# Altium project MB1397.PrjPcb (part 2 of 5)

## Sheet Audio.SchDoc: Audio
size A4; Date: Not used; ApprovedBy: Not used; CheckedBy: Not used; Author: Not used; CompanyName: STMicroelectronics; DrawnBy: Not used; Engineer: Not used; Organization: Not used; Address1: Not used; Address2: Not used; Address3: Not used; Address4: Not used; DocumentNumber: Not used; Revision: Not used; SheetNumber: 9; SheetTotal: 22
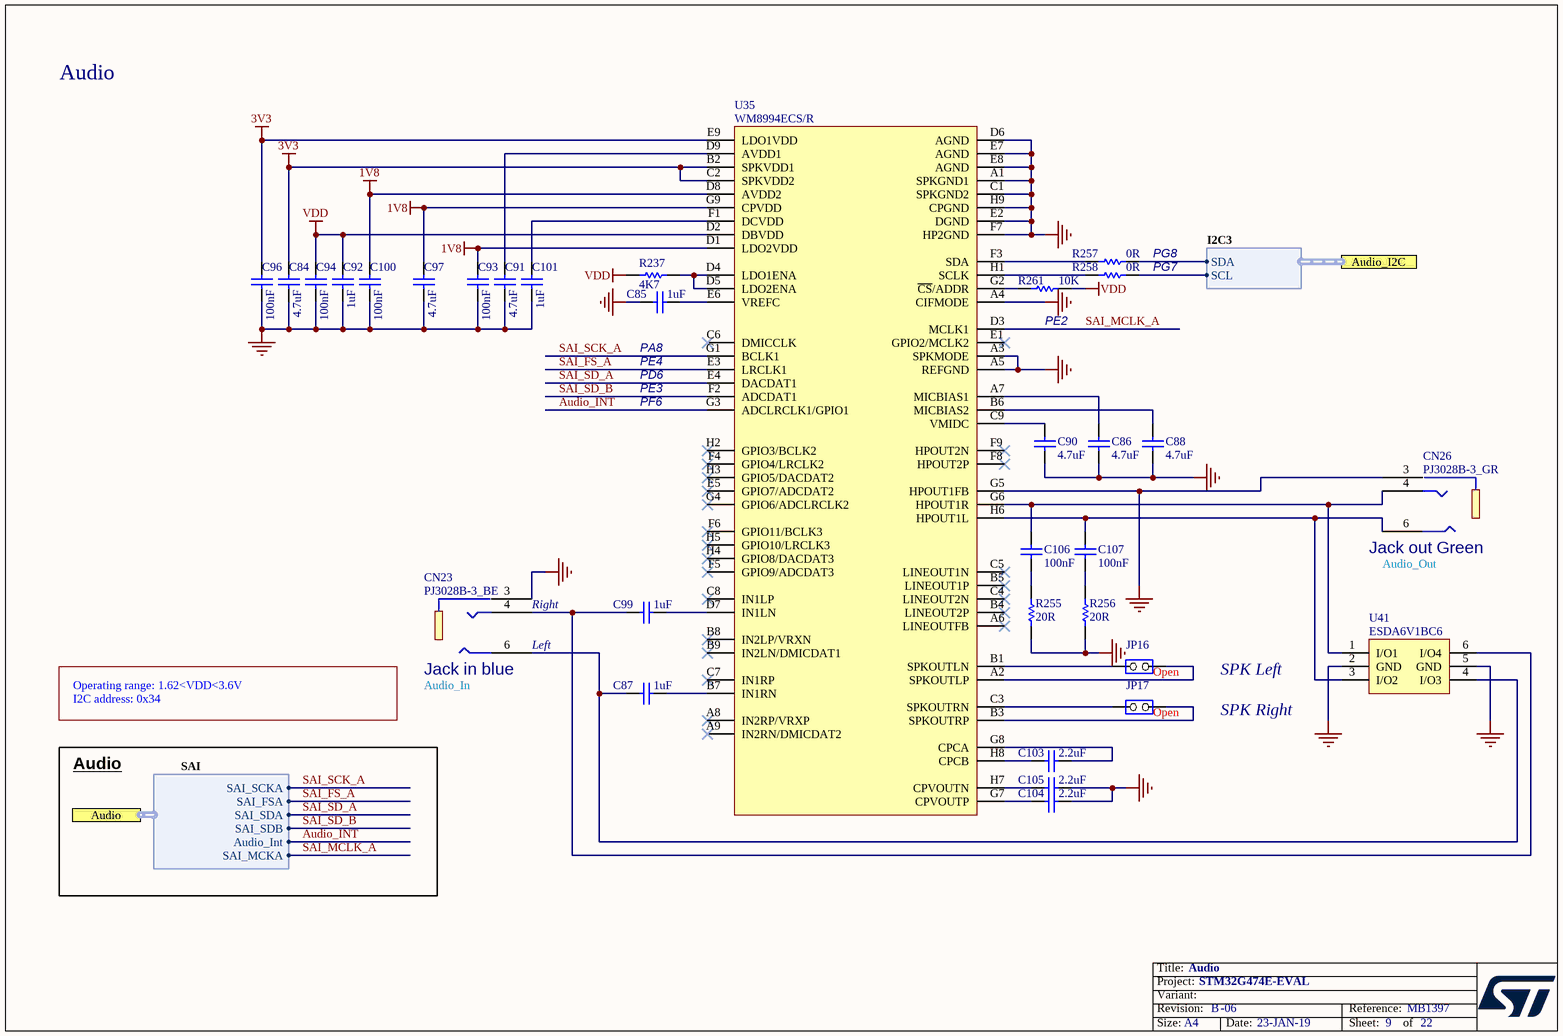
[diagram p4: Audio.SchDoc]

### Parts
C84  value 4.7uF  [C0603]  (hidden comment: Capacitor)
C85  value 1uF  [C0603]  (hidden comment: Capacitor)
C86  value 4.7uF  [C0603]  (hidden comment: Capacitor)
C87  value 1uF  [C0603]  (hidden comment: Capacitor)
C88  value 4.7uF  [C0603]  (hidden comment: Capacitor)
C90  value 4.7uF  [C0603]  (hidden comment: Capacitor)
C91  value 4.7uF  [C0603]  (hidden comment: Capacitor)
C92  value 1uF  [C0603]  (hidden comment: Capacitor)
C93  value 100nF  [C0402]  (hidden comment: Capacitor)
C94  value 100nF  [C0402]  (hidden comment: Capacitor)
C96  value 100nF  [C0402]  (hidden comment: Capacitor)
C97  value 4.7uF  [C0603]  (hidden comment: Capacitor)
C99  value 1uF  [C0603]  (hidden comment: Capacitor)
C100  value 100nF  [C0402]  (hidden comment: Capacitor)
C101  value 1uF  [C0603]  (hidden comment: Capacitor)
C103  value 2.2uF  [C0603]  (hidden comment: Capacitor)
C104  value 2.2uF  [C0603]  (hidden comment: Capacitor)
C105  value 2.2uF  [C0603]  (hidden comment: Capacitor)
C106  value 100nF  [C0402]  (hidden comment: Capacitor)
C107  value 100nF  [C0402]  (hidden comment: Capacitor)
CN23  value PJ3028B-3_BE  [CON_PHONE-JACK-3P5_HY_PJ3028B]  (hidden comment: Jack_PJ3028B-3_3P)
CN26  value PJ3028B-3_GR  [CON_PHONE-JACK-3P5_HY_PJ3028B]  (hidden comment: Jack_PJ3028B-3_3P)
JP16  Jumper_Header 2x1  [CON_SAMTEC_TSW-102-07-G-S]  (value not drawn)
JP17  Jumper_Header 2x1  [CON_SAMTEC_TSW-102-07-G-S]  (value not drawn)
R237  value 4K7  [R0402]  (hidden comment: Resistor)
R255  value 20R  [R0603]  (hidden comment: Resistor)
R256  value 20R  [R0603]  (hidden comment: Resistor)
R257  value 0R  [R0603]  (hidden comment: Resistor)
R258  value 0R  [R0603]  (hidden comment: Resistor)
R261  value 10K  [R0402]  (hidden comment: Resistor)
U35  WM8994ECS/R  [ICC_W-CSP-BGA72_4P511X4P023_P050]
U41  ESDA6V1BC6  [ESD_SOT23-6L]

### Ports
Audio (harness SAI), Audio_I2C (harness I2C3)

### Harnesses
I2C3: SDA, SCL
SAI: SAI_SDB, SAI_FSA, Audio_Int, SAI_SDA, SAI_SCKA, SAI_MCKA

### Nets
1V8: C93.1 C97.2 C100.1 U35.D1(LDO2VDD) U35.D8(AVDD2) U35.G9(CPVDD)
3V3: C84.2 C96.1 U35.B2(SPKVDD1) U35.C2(SPKVDD2) U35.E9(LDO1VDD)
GND: C84.1 C85.2 C86.1 C88.1 C90.1 C91.1 C92.1 C93.2 C94.2 C96.2 C97.1 C100.2 C101.1 C104.1 C105.1 CN23.3 CN26.3 R255.1 R256.1 U35.A1(SPKGND1) U35.A3(SPKMODE) U35.A4(CIFMODE) U35.A5(REFGND) U35.C1(SPKGND2) U35.D6(AGND) U35.E2(DGND) U35.E7(AGND) U35.E8(AGND) U35.F7(HP2GND) U35.G5(HPOUT1FB) U35.H9(CPGND) U41.2(GND) U41.5(GND)
VDD: C92.2 C94.1 R237.1 R261.1 U35.D2(DBVDD)
Audio_INT: U35.G3(ADCLRCLK1/GPIO1) ; port Audio.Audio_Int
SAI_FS_A: U35.E3(LRCLK1) ; port Audio.SAI_FSA
SAI_MCLK_A: U35.D3(MCLK1) ; port Audio.SAI_MCKA
SAI_SCK_A: U35.G1(BCLK1) ; port Audio.SAI_SCKA
SAI_SD_A: U35.E4(DACDAT1) ; port Audio.SAI_SDA
SAI_SD_B: U35.F2(ADCDAT1) ; port Audio.SAI_SDB
NetC85_1: C85.1 U35.E6(VREFC)
NetC86_2: C86.2 U35.A7(MICBIAS1)
NetC87_1: C87.1 U35.B7(IN1RN)
NetC87_2: C87.2 CN23.6 U41.4(I/O3)
NetC88_2: C88.2 U35.B6(MICBIAS2)
NetC90_2: C90.2 U35.C9(VMIDC)
NetC91_2: C91.2 U35.D9(AVDD1)
NetC99_1: C99.1 U35.D7(IN1LN)
NetC99_2: C99.2 CN23.4 U41.6(I/O4)
NetC101_2: C101.2 U35.F1(DCVDD)
NetC103_1: C103.1 U35.G8(CPCA)
NetC103_2: C103.2 U35.H8(CPCB)
NetC104_2: C104.2 U35.G7(CPVOUTP)
NetC105_2: C105.2 U35.H7(CPVOUTN)
NetC106_1: C106.1 CN26.4 U35.G6(HPOUT1R) U41.1(I/O1)
NetC106_2: C106.2 R255.2
NetC107_1: C107.1 CN26.6 U35.H6(HPOUT1L) U41.3(I/O2)
NetC107_2: C107.2 R256.2
NetJP16_1: JP16.1(COMMON) U35.A2(SPKOUTLP)
NetJP16_2: JP16.2(NO) U35.B1(SPKOUTLN)
NetJP17_1: JP17.1(COMMON) U35.B3(SPKOUTRP)
NetJP17_2: JP17.2(NO) U35.C3(SPKOUTRN)
NetR237_2: R237.2 U35.D4(LDO1ENA) U35.D5(LDO2ENA)
NetR257_1: R257.1 U35.F3(SDA)
NetR257_2: R257.2 ; port Audio_I2C.SDA
NetR258_1: R258.1 U35.H1(SCLK)
NetR258_2: R258.2 ; port Audio_I2C.SCL
NetR261_2: R261.2 U35.G2(~{CS}/ADDR)

Not connected (* = marked no-connect by the designer): U35 A6(LINEOUTFB)* A8(IN2RP/VRXP)* A9(IN2RN/DMICDAT2)* B4(LINEOUT2P)* B5(LINEOUT1P)* B8(IN2LP/VRXN)* B9(IN2LN/DMICDAT1)* C4(LINEOUT2N)* C5(LINEOUT1N)* C6(DMICCLK)* C7(IN1RP)* C8(IN1LP)* E1(GPIO2/MCLK2)* E5(GPIO7/ADCDAT2)* F4(GPIO4/LRCLK2)* F5(GPIO9/ADCDAT3)* F6(GPIO11/BCLK3)* F8(HPOUT2P)* F9(HPOUT2N)* G4(GPIO6/ADCLRCLK2)* H2(GPIO3/BCLK2)* H3(GPIO5/DACDAT2)* H4(GPIO8/DACDAT3)* H5(GPIO10/LRCLK3)*

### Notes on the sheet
- Audio
- PG8
- PG7
- (near C85) PA8
- PD6
- PE4
- (near R261) PE2
- PE3
- PF6
- (near CN26) Jack out Green
- (near CN26) Audio_Out
- (near CN23) Right
- (near CN23) Left
- Operating range: 1.62<VDD<3.6V
- I2C address: 0x34
- (near CN23) Jack in blue
- (near CN23) Audio_In
- (near JP16) Open
- (near JP17) Open
- SPK Left
- SPK Right

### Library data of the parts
C84 C86 C88 C90 C91 C97 = MCD-00009: Capacitor, MLCC, 4.7uF, 16V, X5R, 10%, 0603, T=0.8mm; Manufacturer_Part_Number: CC0603KRX5R7BB475; Manufacturer: YAGEO; Provided_By: SUBCO; Initial_Board_Reference: MB1274; Path: ws/MCD_ApplicationBoards/Lists/MCDPARTSdatabase; Item Type: Item
C85 C87 C92 C99 C101 = MCD-00010: Capacitor, MLCC, 1uF, 16V, X5R, 10%, 0603, T=0,8mm; Manufacturer_Part_Number: CC0603KRX5R7BB105; Manufacturer: YAGEO; Provided_By: SUBCO; Initial_Board_Reference: MB1274; Path: ws/MCD_ApplicationBoards/Lists/MCDPARTSdatabase; Item Type: Item
C93 C94 C96 C100 C106 C107 = MCD-00006: Capacitor, MLCC, 100nF, 16V, X7R, 10%, 0402, T=0.5mm; Manufacturer_Part_Number: CC0402KRX7R7BB104; Manufacturer: YAGEO; Alternate_Manufacturer_Part_Number: GCM155R71C104KA55D; Alternate_Manufacturer: MURATA; Provided_By: SUBCO; Initial_Board_Reference: MB1274; Path: ws/MCD_ApplicationBoards/Lists/MCDPARTSdatabase; Item Type: Item
C103-C105 = MCD-00012: Capacitor, MLCC, 2.2uF, 10V, X5R, 10%, 0603, T=0,8mm; Manufacturer_Part_Number: CC0603KRX5R6BB225; Manufacturer: YAGEO; Alternate_Manufacturer_Part_Number: C0603C225K8PACTU; Alternate_Manufacturer: KEMET; Provided_By: SUBCO; Initial_Board_Reference: MB1274; Path: ws/MCD_ApplicationBoards/Lists/MCDPARTSdatabase; Item Type: Item
CN23 = MCD-00682: Connector Jack socket Stereo 3.5mm, 3 pins, RA, SMT, Blue (Line input); Manufacturer: QIAOD; Alternate_Manufacturer_Part_Number: PJ30280-3_BE; Provided_By: SUBCO; Initial_Board_Reference: MB1260; Path: ws/MCD_ApplicationBoards/Lists/MCDPARTSdatabase; Item Type: Item
CN26 = MCD-00018: Connector Jack socket Stereo 3.5mm, 3 pins, RA, SMT, Green (Line output); Manufacturer: QIAOD; Alternate_Manufacturer_Part_Number: PJ30280-3_GR; Provided_By: SUBCO; Initial_Board_Reference: MB1274; Path: ws/MCD_ApplicationBoards/Lists/MCDPARTSdatabase; Item Type: Item
JP16 JP17 = MCD-00045: Header, 2x1, 2,54mm, VR, TH, Height 5.84mm/2.54mm; Part_Type: Connector; Manufacturer_Part_Number: TSW-102-07-x-S; Manufacturer: SAMTEC; Value: Shunt not fitted; Provided_By: SUBCO; Initial_Board_Reference: MB1274; Path: ws/MCD_ApplicationBoards/Lists/MCDPARTSdatabase; Item Type: Item
R237 = MCD-00065: Resistor,4K7,0402,1%,1/16W; Manufacturer_Part_Number: RC0402FR-074K7L; Manufacturer: YAGEO; Alternate_Manufacturer_Part_Number: RT0402FRE074K7L; Provided_By: SUBCO; Initial_Board_Reference: MB1274; Path: ws/MCD_ApplicationBoards/Lists/MCDPARTSdatabase; Item Type: Item
R255 R256 = MCD-00345: Resistor,20R,0603,1%,1/10W; Manufacturer_Part_Number: RC0603FR-0720RL; Manufacturer: YAGEO; Provided_By: SUBCO; Initial_Board_Reference: MBxxxx; Path: ws/MCD_ApplicationBoards/Lists/MCDPARTSdatabase; Item Type: Item
R257 R258 = MCD-00056: Resistor,0R,0603,5%,1/10W; Manufacturer_Part_Number: RC0603JR-070RL; Manufacturer: YAGEO; Provided_By: SUBCO; Initial_Board_Reference: MB1274; Path: ws/MCD_ApplicationBoards/Lists/MCDPARTSdatabase; Item Type: Item
R261 = MCD-00053: Resistor,10K,0402,1%,1/16W; Manufacturer_Part_Number: RC0402FR-0710KL; Manufacturer: YAGEO; Provided_By: SUBCO; Initial_Board_Reference: MB1274; Path: ws/MCD_ApplicationBoards/Lists/MCDPARTSdatabase; Item Type: Item
U35 = MCD-00079: Multi-Channel Audio Hub CODEC for Smartphones; Part_Type: IC; Manufacturer: CIRRUS LOGIC; Provided_By: SUBCO; Initial_Board_Reference: MB1274; Path: ws/MCD_ApplicationBoards/Lists/MCDPARTSdatabase; Item Type: Item
U41 = MCD-00247: Quad Bidir ESD protection; Part_Type: Diode; Manufacturer: STMICROELECTRONICS; BMS_Part_Number: 9179038; Provided_By: SUBCO with ST control; Initial_Board_Reference: MB1311; Path: ws/MCD_ApplicationBoards/Lists/MCDPARTSdatabase; Item Type: Item

## Sheet QSPI_Memory.SchDoc: QSPI Memory
size A4; Date: Not used; ApprovedBy: Not used; CheckedBy: Not used; Author: Not used; CompanyName: STMicroelectronics; DrawnBy: Not used; Engineer: Not used; Organization: Not used; Address1: Not used; Address2: Not used; Address3: Not used; Address4: Not used; DocumentNumber: Not used; Revision: Not used; SheetNumber: 8; SheetTotal: 22
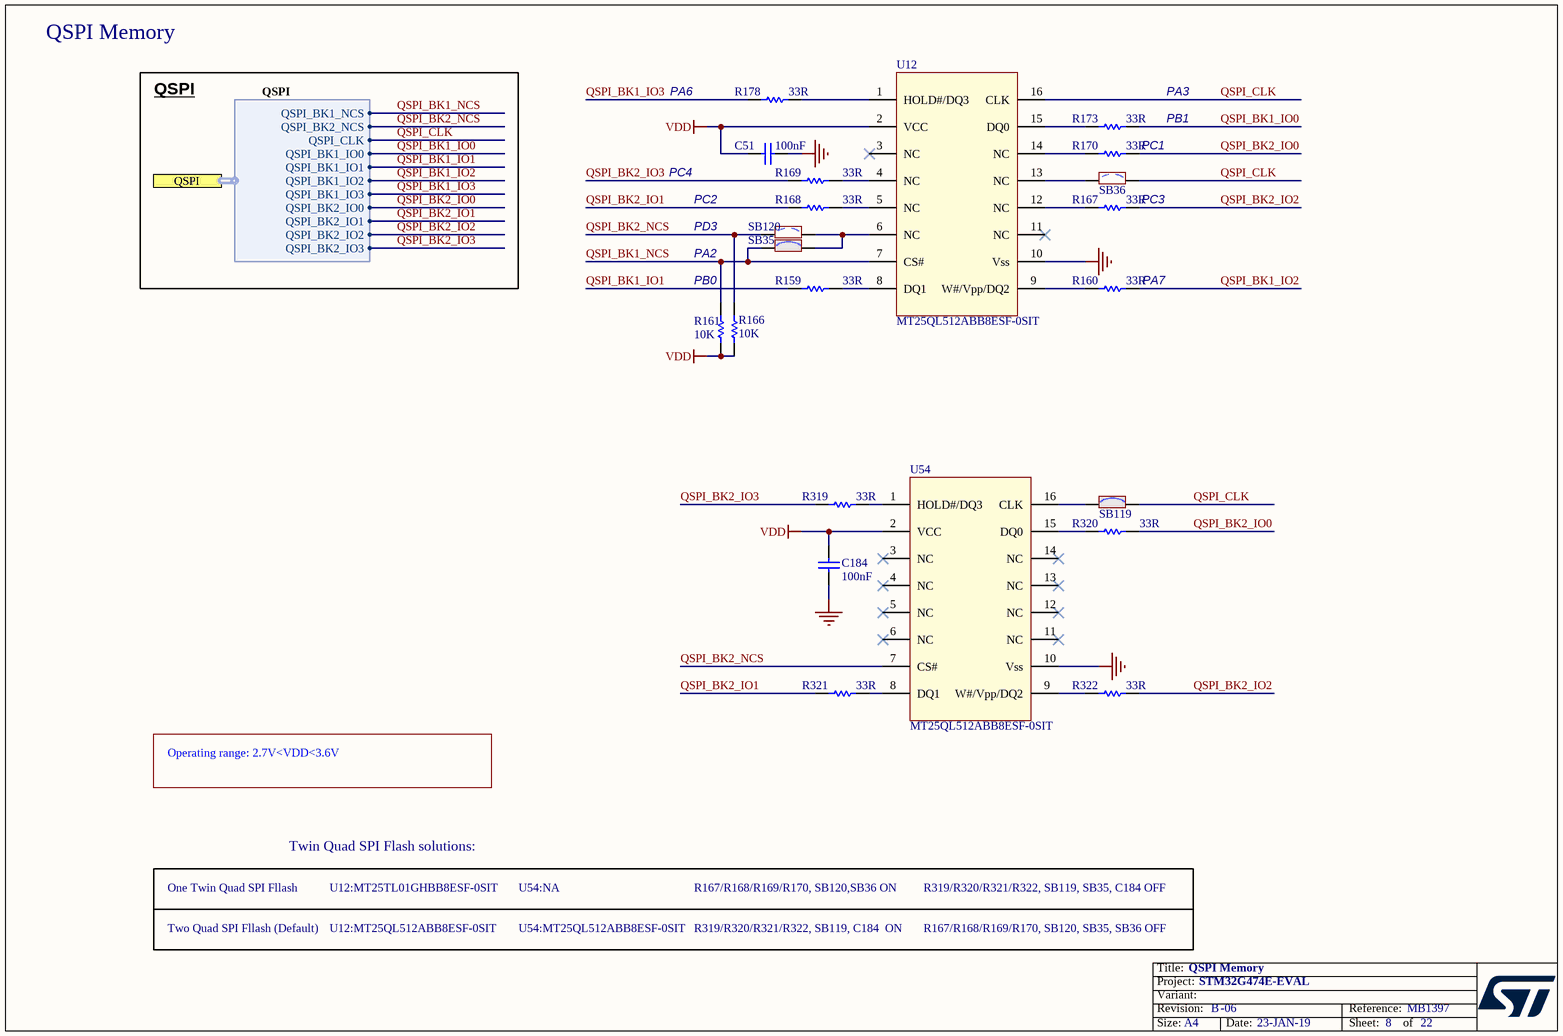
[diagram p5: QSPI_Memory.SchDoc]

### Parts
C51  value 100nF  [C0402]  (hidden comment: Capacitor)
C184  value 100nF  [C0402]  (hidden comment: Capacitor)
R159  value 33R  [R0402]  (hidden comment: Resistor)
R160  value 33R  [R0402]  (hidden comment: Resistor)
R161  value 10K  [R0402]  (hidden comment: Resistor)
R166  value 10K  [R0402]  (hidden comment: Resistor)
R167  value 33R  [R0402]  (hidden comment: Resistor)
R168  value 33R  [R0402]  (hidden comment: Resistor)
R169  value 33R  [R0402]  (hidden comment: Resistor)
R170  value 33R  [R0402]  (hidden comment: Resistor)
R173  value 33R  [R0402]  (hidden comment: Resistor)
R178  value 33R  [R0402]  (hidden comment: Resistor)
R319  value 33R  [R0402]  (hidden comment: Resistor)
R320  value 33R  [R0402]  (hidden comment: Resistor)
R321  value 33R  [R0402]  (hidden comment: Resistor)
R322  value 33R  [R0402]  (hidden comment: Resistor)
SB35  SB_ON  [SOLDER-BRIDGE_R0603-0R]  (value not drawn)
SB36  SB_OFF  [SOLDER-BRIDGE_R0603-0R]  (value not drawn)
SB119  SB_ON  [SOLDER-BRIDGE_R0603-0R]  (value not drawn)
SB120  SB_OFF  [SOLDER-BRIDGE_R0603-0R]  (value not drawn)
U12  MT25QL512ABB8ESF-0SIT  [ICC_SOP2-SF_16P_10P3X7P5_P127]
U54  MT25QL512ABB8ESF-0SIT  [ICC_SOP2-SF_16P_10P3X7P5_P127]

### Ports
QSPI (harness QSPI)

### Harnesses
QSPI: QSPI_BK1_IO1, QSPI_BK1_IO0, QSPI_CLK, QSPI_BK1_NCS, QSPI_BK1_IO2, QSPI_BK1_IO3, QSPI_BK2_IO1, QSPI_BK2_IO0, QSPI_BK2_IO2, QSPI_BK2_IO3, QSPI_BK2_NCS

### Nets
GND: C51.1 C184.1 U12.10(Vss) U54.10(Vss)
VDD: C51.2 C184.2 R161.1 R166.1 U12.2(VCC) U54.2(VCC)
QSPI_BK1_IO0: R173.2 ; port QSPI.QSPI_BK1_IO0
QSPI_BK1_IO1: R159.1 ; port QSPI.QSPI_BK1_IO1
QSPI_BK1_IO2: R160.2 ; port QSPI.QSPI_BK1_IO2
QSPI_BK1_IO3: R178.1 ; port QSPI.QSPI_BK1_IO3
QSPI_BK1_NCS: R161.2 SB35.1 U12.7(CS#) ; port QSPI.QSPI_BK1_NCS
QSPI_BK2_IO0: R170.2 R320.2 ; port QSPI.QSPI_BK2_IO0
QSPI_BK2_IO1: R168.1 R321.1 ; port QSPI.QSPI_BK2_IO1
QSPI_BK2_IO2: R167.2 R322.2 ; port QSPI.QSPI_BK2_IO2
QSPI_BK2_IO3: R169.1 R319.1 ; port QSPI.QSPI_BK2_IO3
QSPI_BK2_NCS: R166.2 SB120.1 U54.7(CS#) ; port QSPI.QSPI_BK2_NCS
QSPI_CLK: SB36.2 SB119.2 U12.16(CLK) ; port QSPI.QSPI_CLK
NetR159_2: R159.2 U12.8(DQ1)
NetR160_1: R160.1 U12.9(W#/Vpp/DQ2)
NetR167_1: R167.1 U12.12(NC)
NetR168_2: R168.2 U12.5(NC)
NetR169_2: R169.2 U12.4(NC)
NetR170_1: R170.1 U12.14(NC)
NetR173_1: R173.1 U12.15(DQ0)
NetR178_2: R178.2 U12.1(HOLD#/DQ3)
NetR319_2: R319.2 U54.1(HOLD#/DQ3)
NetR320_1: R320.1 U54.15(DQ0)
NetR321_2: R321.2 U54.8(DQ1)
NetR322_1: R322.1 U54.9(W#/Vpp/DQ2)
NetSB35_2: SB35.2 SB120.2 U12.6(NC)
NetSB36_1: SB36.1 U12.13(NC)
NetSB119_1: SB119.1 U54.16(CLK)

Not connected (* = marked no-connect by the designer): U12 3(NC)* 11(NC)*; U54 3(NC)* 4(NC)* 5(NC)* 6(NC)* 11(NC)* 12(NC)* 13(NC)* 14(NC)*

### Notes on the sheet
- QSPI Memory
- QSPI
- PA6
- PA3
- (near C51) PC4
- PB1
- PC1
- PC2
- PD3
- PC3
- PB0
- PA2
- (near R160) PA7
- Operating range: 2.7V<VDD<3.6V
- Twin Quad SPI Flash solutions:
- One Twin Quad SPI Fllash
- U12:MT25TL01GHBB8ESF-0SIT
- U54:NA
- R167/R168/R169/R170, SB120,SB36 ON
- R319/R320/R321/R322, SB119, SB35, C184 OFF
- Two Quad SPI Fllash (Default)
- U12:MT25QL512ABB8ESF-0SIT
- U54:MT25QL512ABB8ESF-0SIT
- R319/R320/R321/R322, SB119, C184  ON
- R167/R168/R169/R170, SB120, SB35, SB36 OFF

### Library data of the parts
C51 C184 = MCD-00006: as C93 on sheet Audio
R159 R160 R167-R170 R173 R178 R319-R322 = MCD-00455: Resistor,33R,0402,1%,1/16W; Manufacturer_Part_Number: RC0402FR-0733RL; Manufacturer: YAGEO; Provided_By: SUBCO; Initial_Board_Reference: MBxxxx; Path: ws/MCD_ApplicationBoards/Lists/MCDPARTSdatabase; Item Type: Item
R161 R166 = MCD-00053: as R261 on sheet Audio
SB35 SB119 = MCD-00071: Solder Bridge ON; Part_Type: Mechanical; Manufacturer_Part_Number: RC0603JR-070RL; Manufacturer: YAGEO; Provided_By: SUBCO; Initial_Board_Reference: MB1274; Path: ws/MCD_ApplicationBoards/Lists/MCDPARTSdatabase; Item Type: Item
SB36 SB120 = MCD-00072: Solder Bridge OFF; Part_Type: Mechanical; Manufacturer_Part_Number: RC0603JR-070RL; Manufacturer: YAGEO; Provided_By: SUBCO; Initial_Board_Reference: MB1274; Path: ws/MCD_ApplicationBoards/Lists/MCDPARTSdatabase; Item Type: Item
U12 U54 = MCD-01128: Micron Serial NOR Flash Memory; Part_Type: IC; BMS_Part_Number: 9171976; Provided_By: SUBCO; Initial_Board_Reference: MB1381; Path: ws/MCD_ApplicationBoards/Lists/MCDPARTSdatabase; Item Type: Item

## Sheet FDCAN.SchDoc: FDCAN
size A4; Date: Not used; ApprovedBy: Not used; CheckedBy: Not used; Author: Not used; CompanyName: STMicroelectronics; DrawnBy: Not used; Engineer: Not used; Organization: Not used; Address1: Not used; Address2: Not used; Address3: Not used; Address4: Not used; DocumentNumber: Not used; Revision: Not used; SheetNumber: 12; SheetTotal: 22
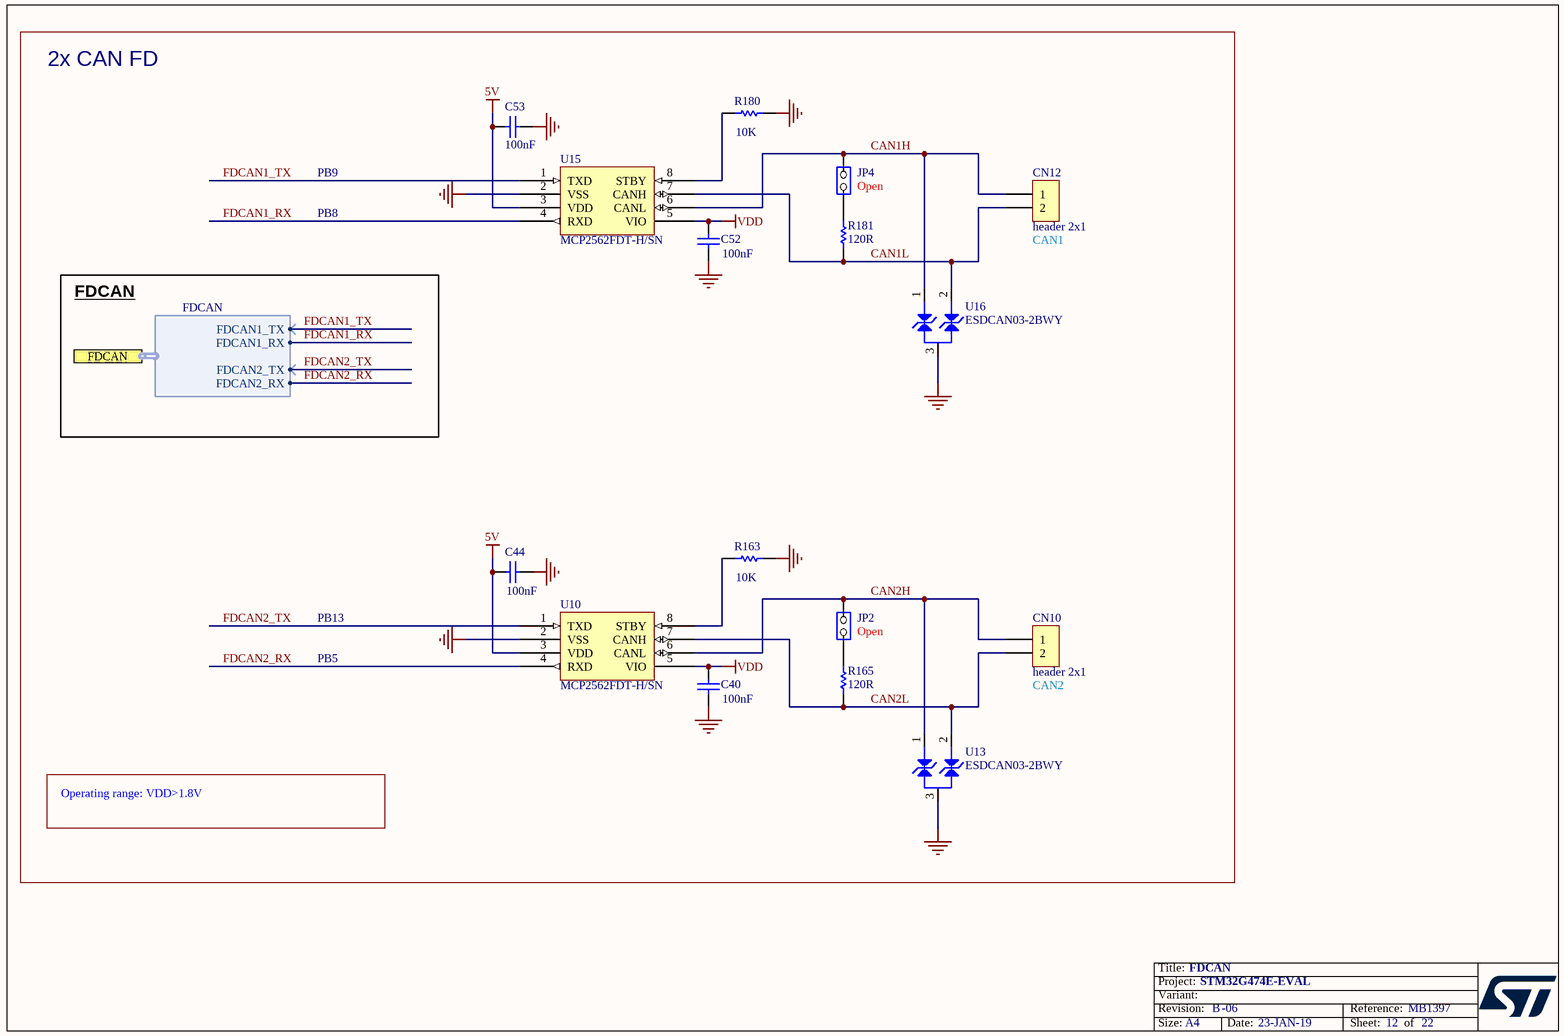
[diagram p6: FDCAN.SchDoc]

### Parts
C40  value 100nF  [C0402]  (hidden comment: Capacitor)
C44  value 100nF  [C0402]  (hidden comment: Capacitor)
C52  value 100nF  [C0402]  (hidden comment: Capacitor)
C53  value 100nF  [C0402]  (hidden comment: Capacitor)
CN10  Header 2x1  [CON_988-JIUBABA_PHFS25-11-02-G0B115-T-1]
CN12  Header 2x1  [CON_988-JIUBABA_PHFS25-11-02-G0B115-T-1]
JP2  Jumper_Header 2x1  [CON_SAMTEC_TSW-102-07-G-S]  (value not drawn)
JP4  Jumper_Header 2x1  [CON_SAMTEC_TSW-102-07-G-S]  (value not drawn)
R163  value 10K  [R0402]  (hidden comment: Resistor)
R165  value 120R  [R0603]  (hidden comment: Resistor)
R180  value 10K  [R0402]  (hidden comment: Resistor)
R181  value 120R  [R0603]  (hidden comment: Resistor)
U10  value MCP2562FDT-H/SN  [ICC_SO8_5X4_P127]  (hidden comment: MCP2562FD)
U13  value ESDCAN03-2BWY  [DIO_SOT323]  (hidden comment: ESD-TRANSIL-DUAL-BIDIR)
U15  value MCP2562FDT-H/SN  [ICC_SO8_5X4_P127]  (hidden comment: MCP2562FD)
U16  value ESDCAN03-2BWY  [DIO_SOT323]  (hidden comment: ESD-TRANSIL-DUAL-BIDIR)

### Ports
FDCAN (harness FDCAN)

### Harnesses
FDCAN: FDCAN1_TX, FDCAN1_RX, FDCAN2_TX, FDCAN2_RX

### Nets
5V: C44.1 C53.1 U10.3(VDD) U15.3(VDD)
GND: C40.2 C44.2 C52.2 C53.2 R163.2 R180.2 U10.2(VSS) U13.3 U15.2(VSS) U16.3
VDD: C40.1 C52.1 U10.5(VIO) U15.5(VIO)
CAN1H: CN12.1 JP4.2(NO) U15.6(CANL) U16.1
CAN1L: CN12.2 R181.1 U15.7(CANH) U16.2
CAN2H: CN10.1 JP2.2(NO) U10.6(CANL) U13.1
CAN2L: CN10.2 R165.1 U10.7(CANH) U13.2
FDCAN1_RX: U15.4(RXD) ; port FDCAN.FDCAN1_RX
FDCAN1_TX: U15.1(TXD) ; port FDCAN.FDCAN1_TX
FDCAN2_RX: U10.4(RXD) ; port FDCAN.FDCAN2_RX
FDCAN2_TX: U10.1(TXD) ; port FDCAN.FDCAN2_TX
NetJP2_1: JP2.1(COMMON) R165.2
NetJP4_1: JP4.1(COMMON) R181.2
NetR163_1: R163.1 U10.8(STBY)
NetR180_1: R180.1 U15.8(STBY)

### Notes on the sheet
- 2x CAN FD
- PB9
- PB8
- (near JP4) Open
- (near CN12) CAN1
- FDCAN
- PB13
- (near JP2) Open
- PB5
- (near CN10) CAN2
- Operating range: VDD>1.8V

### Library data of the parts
C40 C44 C52 C53 = MCD-00006: as C93 on sheet Audio
CN10 CN12 = MCD-00314: Header, 2x1, 2.54mm, VR, TH, Height 6mm/3mm; Part_Type: Connector; Manufacturer_Part_Number: PHFS25-11-02-G0B115-T-1; Manufacturer: JIUBABA; Provided_By: SUBCO; Initial_Board_Reference: MB1311; Path: ws/MCD_ApplicationBoards/Lists/MCDPARTSdatabase; Item Type: Item
JP2 JP4 = MCD-00045: Header, 2x1, 2,54mm, VR, TH, Height 5.84mm/2.54mm; Manufacturer_Part_Number: TSW-102-07-x-S; Manufacturer: SAMTEC; Part_Type: Connector; Value: Shunt not fitted; Provided_By: SUBCO; Initial_Board_Reference: MB1274; Path: ws/MCD_ApplicationBoards/Lists/MCDPARTSdatabase; Item Type: Item
R163 R180 = MCD-00053: as R261 on sheet Audio
R165 R181 = MCD-00338: Resistor,120R,0603,1%,1/10W; Manufacturer_Part_Number: RC0603FR-07120RL; Manufacturer: YAGEO; BMS_Part_Number: 9129734; Provided_By: SUBCO; Initial_Board_Reference: MBxxxx; Path: ws/MCD_ApplicationBoards/Lists/MCDPARTSdatabase; Item Type: Item
U10 U15 = MCD-00129: High-Speed CAN Flexible Data Rate Transceiver; Manufacturer: MICROCHIP; Part_Type: IC; Provided_By: SUBCO; Initial_Board_Reference: MB1262; Path: ws/MCD_ApplicationBoards/Lists/MCDPARTSdatabase; Item Type: Item
U13 U16 = MCD-01228: Automotive dual-line Transil, transient voltage suppressor (TVS) for CAN bus. Compliant with interfaces in automotive: CAN-FD, LIN, FlexRay, MOST, SENT, USB; Part_Type: Diode; Manufacturer: STMICROELECTRONICS; Provided_By: SUBCO with ST control; Initial_Board_Reference: MB1397; Path: ws/MCD_ApplicationBoards/Lists/MCDPARTSdatabase; Item Type: Item

## Sheet LCD&SDcard.SchDoc: LCD & SD Card
size A4; Date: Not used; ApprovedBy: Not used; CheckedBy: Not used; Author: Not used; CompanyName: STMicroelectronics; DrawnBy: Not used; Engineer: Not used; Organization: Not used; Address1: Not used; Address2: Not used; Address3: Not used; Address4: Not used; DocumentNumber: Not used; Revision: Not used; SheetNumber: 10; SheetTotal: 22
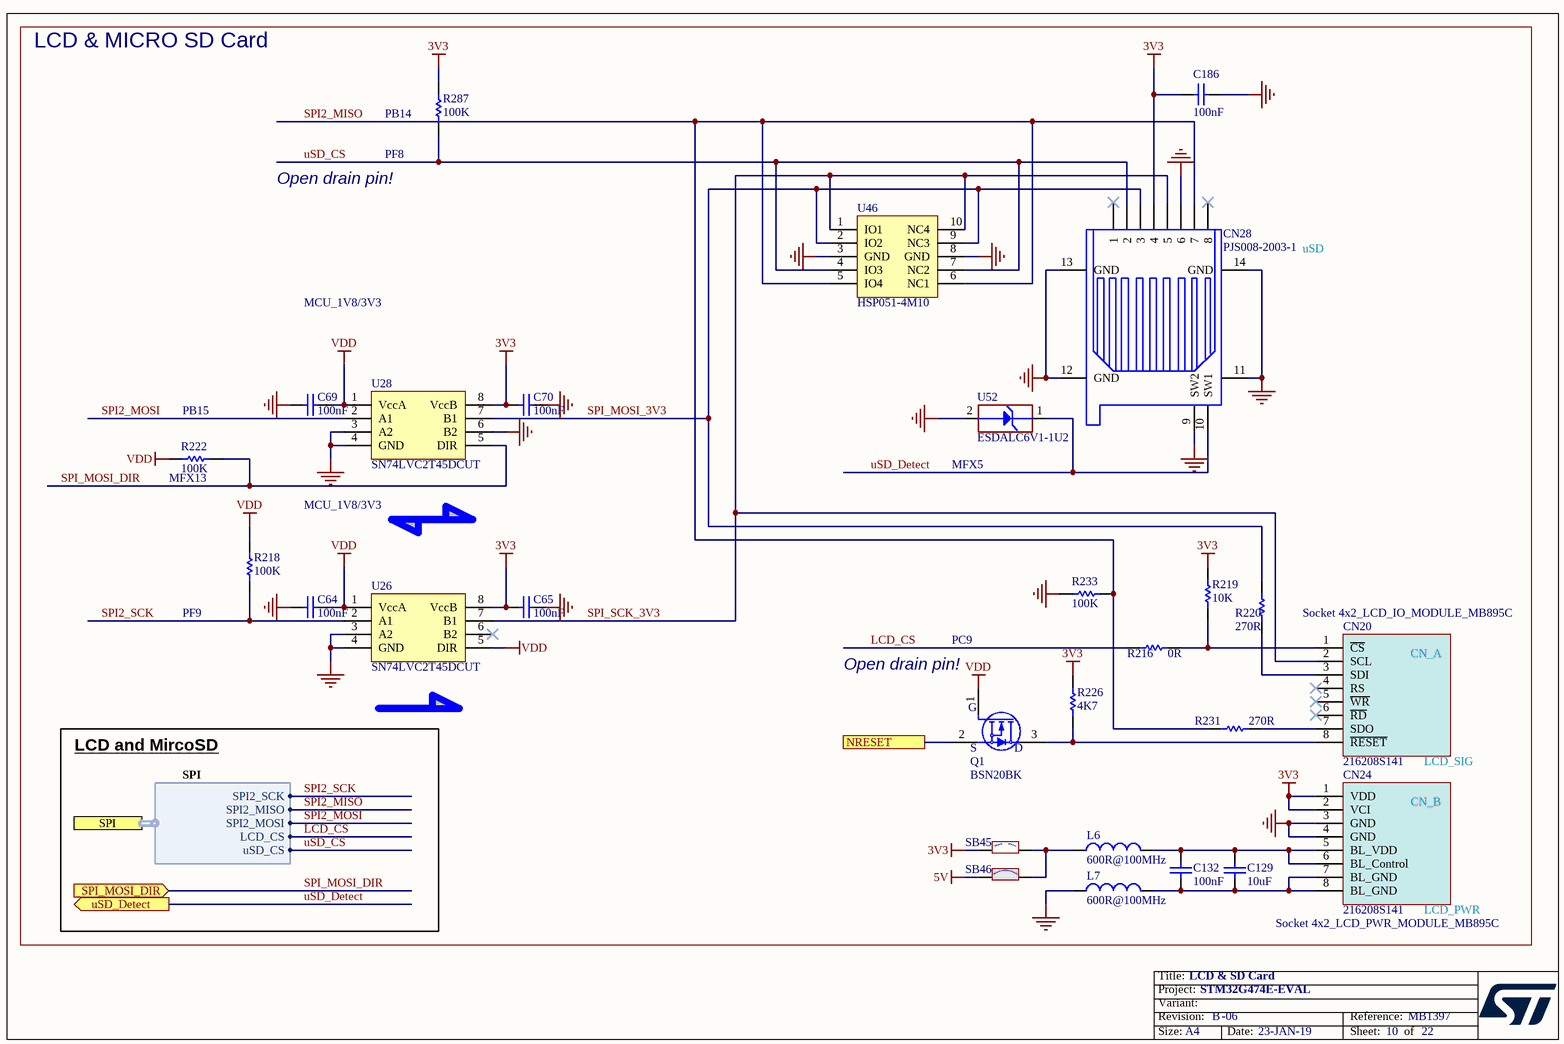
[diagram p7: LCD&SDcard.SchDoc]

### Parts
C64  value 100nF  [C0603]  (hidden comment: Capacitor)
C65  value 100nF  [C0603]  (hidden comment: Capacitor)
C69  value 100nF  [C0603]  (hidden comment: Capacitor)
C70  value 100nF  [C0603]  (hidden comment: Capacitor)
C129  value 10uF  [C0805]  (hidden comment: Capacitor)
C132  value 100nF  [C0402]  (hidden comment: Capacitor)
C186  value 100nF  [C0402]  (hidden comment: Capacitor)
CN20  Socket 4x2_LCD_IO_MODULE_MB895C  value 216208S141  [CON_SOCKET-LCD_LYCN_216208S141]
CN24  Socket 4x2_LCD_PWR_MODULE_MB895C  value 216208S141  [CON_SOCKET-LCD_LYCN_216208S141]
CN28  value PJS008-2003-1  [CON_MICROSD_YAMAICHI_PJS008-2003-1]  (hidden comment: microSD-PJS008-2003)
L6  value 600R@100MHz  [L0603]  (hidden comment: BEAD)
L7  value 600R@100MHz  [L0603]  (hidden comment: BEAD)
Q1  value BSN20BK  [MOS_SOT23]  (hidden comment: BSN20)
R216  value 0R  [R0603]  (hidden comment: Resistor)
R218  value 100K  [R0603]  (hidden comment: Resistor)
R219  value 10K  [R0603]  (hidden comment: Resistor)
R220  value 270R  [R0603]  (hidden comment: Resistor)
R222  value 100K  [R0603]  (hidden comment: Resistor)
R226  value 4K7  [R0402]  (hidden comment: Resistor)
R231  value 270R  [R0603]  (hidden comment: Resistor)
R233  value 100K  [R0603]  (hidden comment: Resistor)
R287  value 100K  [R0603]  (hidden comment: Resistor)
SB45  SB_OFF  [SOLDER-BRIDGE_R0603-0R]  (value not drawn)
SB46  SB_ON  [SOLDER-BRIDGE_R0603-0R]  (value not drawn)
U26  SN74LVC2T45DCUT  [ICC_VSSOP8_DCU_R-PDSO-G8_2X2P30_P050]
U28  SN74LVC2T45DCUT  [ICC_VSSOP8_DCU_R-PDSO-G8_2X2P30_P050]
U46  HSP051-4M10  [ESD_UQFN-10L_2P5X1_P050]
U52  value ESDALC6V1-1U2  [ESD_ST0201]  (hidden comment: ESD-TRANSIL)

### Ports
NRESET, SPI (harness SPI), SPI_MOSI_DIR (in), uSD_Detect (out)

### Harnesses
SPI: SPI2_SCK, SPI2_MISO, SPI2_MOSI, LCD_CS, uSD_CS

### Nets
3V3: C65.2 C70.2 C186.1 CN24.1(VDD) CN24.2(VCI) CN28.4 R219.2 R226.1 R287.2 SB45.1 U26.8(VccB) U28.8(VccB)
5V: SB46.1
GND: C64.2 C65.1 C69.2 C70.1 C186.2 CN24.3(GND) CN24.4(GND) CN28.6 CN28.9(SW2) CN28.11(GND) CN28.12(GND) CN28.13(GND) CN28.14(GND) L7.1 R233.2 U26.3(A2) U26.4(GND) U28.3(A2) U28.4(GND) U28.6(B2) U46.3(GND) U46.8(GND) U52.2(GND)
VDD: C64.1 C69.1 Q1.1(G) R218.2 R222.2 U26.1(VccA) U26.5(DIR) U28.1(VccA)
LCD_CS: R216.1 ; port SPI.LCD_CS
SPI2_MISO: CN28.7 R231.1 R233.1 U46.5(IO4) U46.6(NC1) ; port SPI.SPI2_MISO
SPI2_MOSI: U28.2(A1) ; port SPI.SPI2_MOSI
SPI2_SCK: R218.1 U26.2(A1) ; port SPI.SPI2_SCK
SPI_MOSI_3V3: CN28.3 R220.1 U28.7(B1) U46.2(IO2) U46.9(NC3)
SPI_MOSI_DIR: R222.1 U28.5(DIR) ; port SPI_MOSI_DIR
SPI_SCK_3V3: CN20.2(SCL) CN28.5 U26.7(B1) U46.1(IO1) U46.10(NC4)
uSD_CS: CN28.2 R287.1 U46.4(IO3) U46.7(NC2) ; port SPI.uSD_CS
uSD_Detect: CN28.10(SW1) U52.1(IO1) ; port uSD_Detect
NetC129_1: C129.1 C132.2 CN24.5(BL_VDD) CN24.6(BL_Control) L6.2
NetC129_2: C129.2 C132.1 CN24.7(BL_GND) CN24.8(BL_GND) L7.2
NetCN20_1: CN20.1(~{CS}) R216.2 R219.1
NetCN20_3: CN20.3(SDI) R220.2
NetCN20_7: CN20.7(SDO) R231.2
NetCN20_8: CN20.8(~{RESET}) Q1.3(D) R226.2
NetL6_1: L6.1 SB45.2 SB46.2
NetQ1_2: Q1.2(S) ; port NRESET

Not connected (* = marked no-connect by the designer): CN20 4(RS)* 5(~{WR})* 6(~{RD})*; CN28 1* 8*; U26 6(B2)*

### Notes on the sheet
- LCD & MICRO SD Card
- (near R287) PB14
- Open drain pin!
- (near R287) PF8
- uSD
- MCU_1V8/3V3
- (near R222) PB15
- (near R222) MFX13
- (near U52) MFX5
- PF9
- PC9
- (near Q1) Open drain pin!
- LCD and MircoSD
- LCD_SIG
- LCD_PWR

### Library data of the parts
C64 C65 C69 C70 = MCD-00211: Capacitor, MLCC, 100nF, 16V, X7R, 10%, 0603, T=0,8mm; Manufacturer_Part_Number: CC0603KRX7R7BB104; Manufacturer: YAGEO; Provided_By: SUBCO; Initial_Board_Reference: MB1319; Path: ws/MCD_ApplicationBoards/Lists/MCDPARTSdatabase; Item Type: Item
C129 = MCD-00014: Capacitor, MLCC, 10uF, 25V, X5R, 10%, 0805, T=0,85mm; Manufacturer_Part_Number: CC0805KRX5R8BB106; Manufacturer: YAGEO; Provided_By: SUBCO; Initial_Board_Reference: MB1274; Path: ws/MCD_ApplicationBoards/Lists/MCDPARTSdatabase; Item Type: Item
C132 C186 = MCD-00006: as C93 on sheet Audio
CN20 = MCD-01174: Socket, 4x2, 2.54mm, VR, TH, Height 6.8mm, Double row; Part_Type: Connector; Manufacturer: LYCN; Provided_By: SUBCO; Initial_Board_Reference: MB1397; Path: ws/MCD_ApplicationBoards/Lists/MCDPARTSdatabase; Item Type: Item
CN24 = MCD-01195: socket, 4x2, 2.54mm, VR, TH, Height 6.8mm, Double row; Part_Type: Connector; Manufacturer: LYCN; Provided_By: SUBCO; Initial_Board_Reference: MB1397; Remark: same footprint as MCD-01174; Path: ws/MCD_ApplicationBoards/Lists/MCDPARTSdatabase; Item Type: Item
CN28 = MCD-00023: MicroSD Card Conn, Reversed-Type, Mnt Push-Push, Positionning holes; Manufacturer: YAMAICHI; Part_Type: Connector; Provided_By: SUBCO; Initial_Board_Reference: MB1274; Path: ws/MCD_ApplicationBoards/Lists/MCDPARTSdatabase; Item Type: Item
L6 L7 = MCD-00047: SMD Chip ferrite bead, 600R@100MHz +/-25%, 350mA, 500mohm DC, 0603, T=0.8mm; Part_Type: Inductor; Manufacturer_Part_Number: FCM1608KF-601T03; Manufacturer: TAI-TECH; Provided_By: SUBCO; Initial_Board_Reference: MB1274; Path: ws/MCD_ApplicationBoards/Lists/MCDPARTSdatabase; Item Type: Item
Q1 = MCD-01969: Transistor, N-channel enhancement mode field-effect transistor; Part_Preference: Recommended; Manufacturer: NEXPERIA; Order_Code_RS: 136-4845; Component_Country_Of_Origin: China; ShowFields: YES; ID: 4069
R216 = MCD-00056: as R257 on sheet Audio
R218 R222 R233 R287 = MCD-00223: Resistor,100K,0603,1%,1/10W; Manufacturer_Part_Number: RC0603FR-07100KL; Manufacturer: YAGEO; Provided_By: SUBCO; Initial_Board_Reference: MB1319; Path: ws/MCD_ApplicationBoards/Lists/MCDPARTSdatabase; Item Type: Item
R219 = MCD-00220: Resistor,10K,0603,1%,1/10W; Manufacturer_Part_Number: RC0603FR-0710KL; Manufacturer: YAGEO; Provided_By: SUBCO; Initial_Board_Reference: MB1319; Path: ws/MCD_ApplicationBoards/Lists/MCDPARTSdatabase; Item Type: Item
R220 R231 = MCD-00442: Resistor,270R,0603,1%,1/10W; Manufacturer_Part_Number: RC0603FR-07270RL; Manufacturer: YAGEO; Provided_By: SUBCO; Initial_Board_Reference: MBxxxx; Path: ws/MCD_ApplicationBoards/Lists/MCDPARTSdatabase; Item Type: Item
R226 = MCD-00065: as R237 on sheet Audio
SB45 = MCD-00072: as SB36 on sheet QSPI_Memory
SB46 = MCD-00071: as SB35 on sheet QSPI_Memory
U26 U28 = MCD-00264: Dual bit dual supply bus transceiver; Part_Type: IC; Manufacturer: TEXAS INSTRUMENTS; Provided_By: SUBCO; Initial_Board_Reference: MB1319; Path: ws/MCD_ApplicationBoards/Lists/MCDPARTSdatabase; Item Type: Item
U46 = MCD-00667: 4-line ESD protection for high speed lines; Manufacturer: STMICROELECTRONICS; Part_Type: Diode; BMS_Part_Number: 9179041; Provided_By: SUBCO with ST control; Initial_Board_Reference: MB1331; Path: ws/MCD_ApplicationBoards/Lists/MCDPARTSdatabase; Item Type: Item
U52 = MCD-00170: ESD protection 6V1; Part_Type: Diode; Manufacturer: STMICROELECTRONICS; BMS_Part_Number: 9151132; Provided_By: SUBCO with ST control; Initial_Board_Reference: MB1274; Path: ws/MCD_ApplicationBoards/Lists/MCDPARTSdatabase; Item Type: Item

## Sheet MotorControl.SchDoc: Motor Control
size A3; Date: Not used; ApprovedBy: Not used; CheckedBy: Not used; Author: Not used; CompanyName: STMicroelectronics; DrawnBy: Not used; Engineer: Not used; Organization: Not used; Address1: Not used; Address2: Not used; Address3: Not used; Address4: Not used; DocumentNumber: Not used; Revision: Not used; SheetNumber: 16; SheetTotal: 22
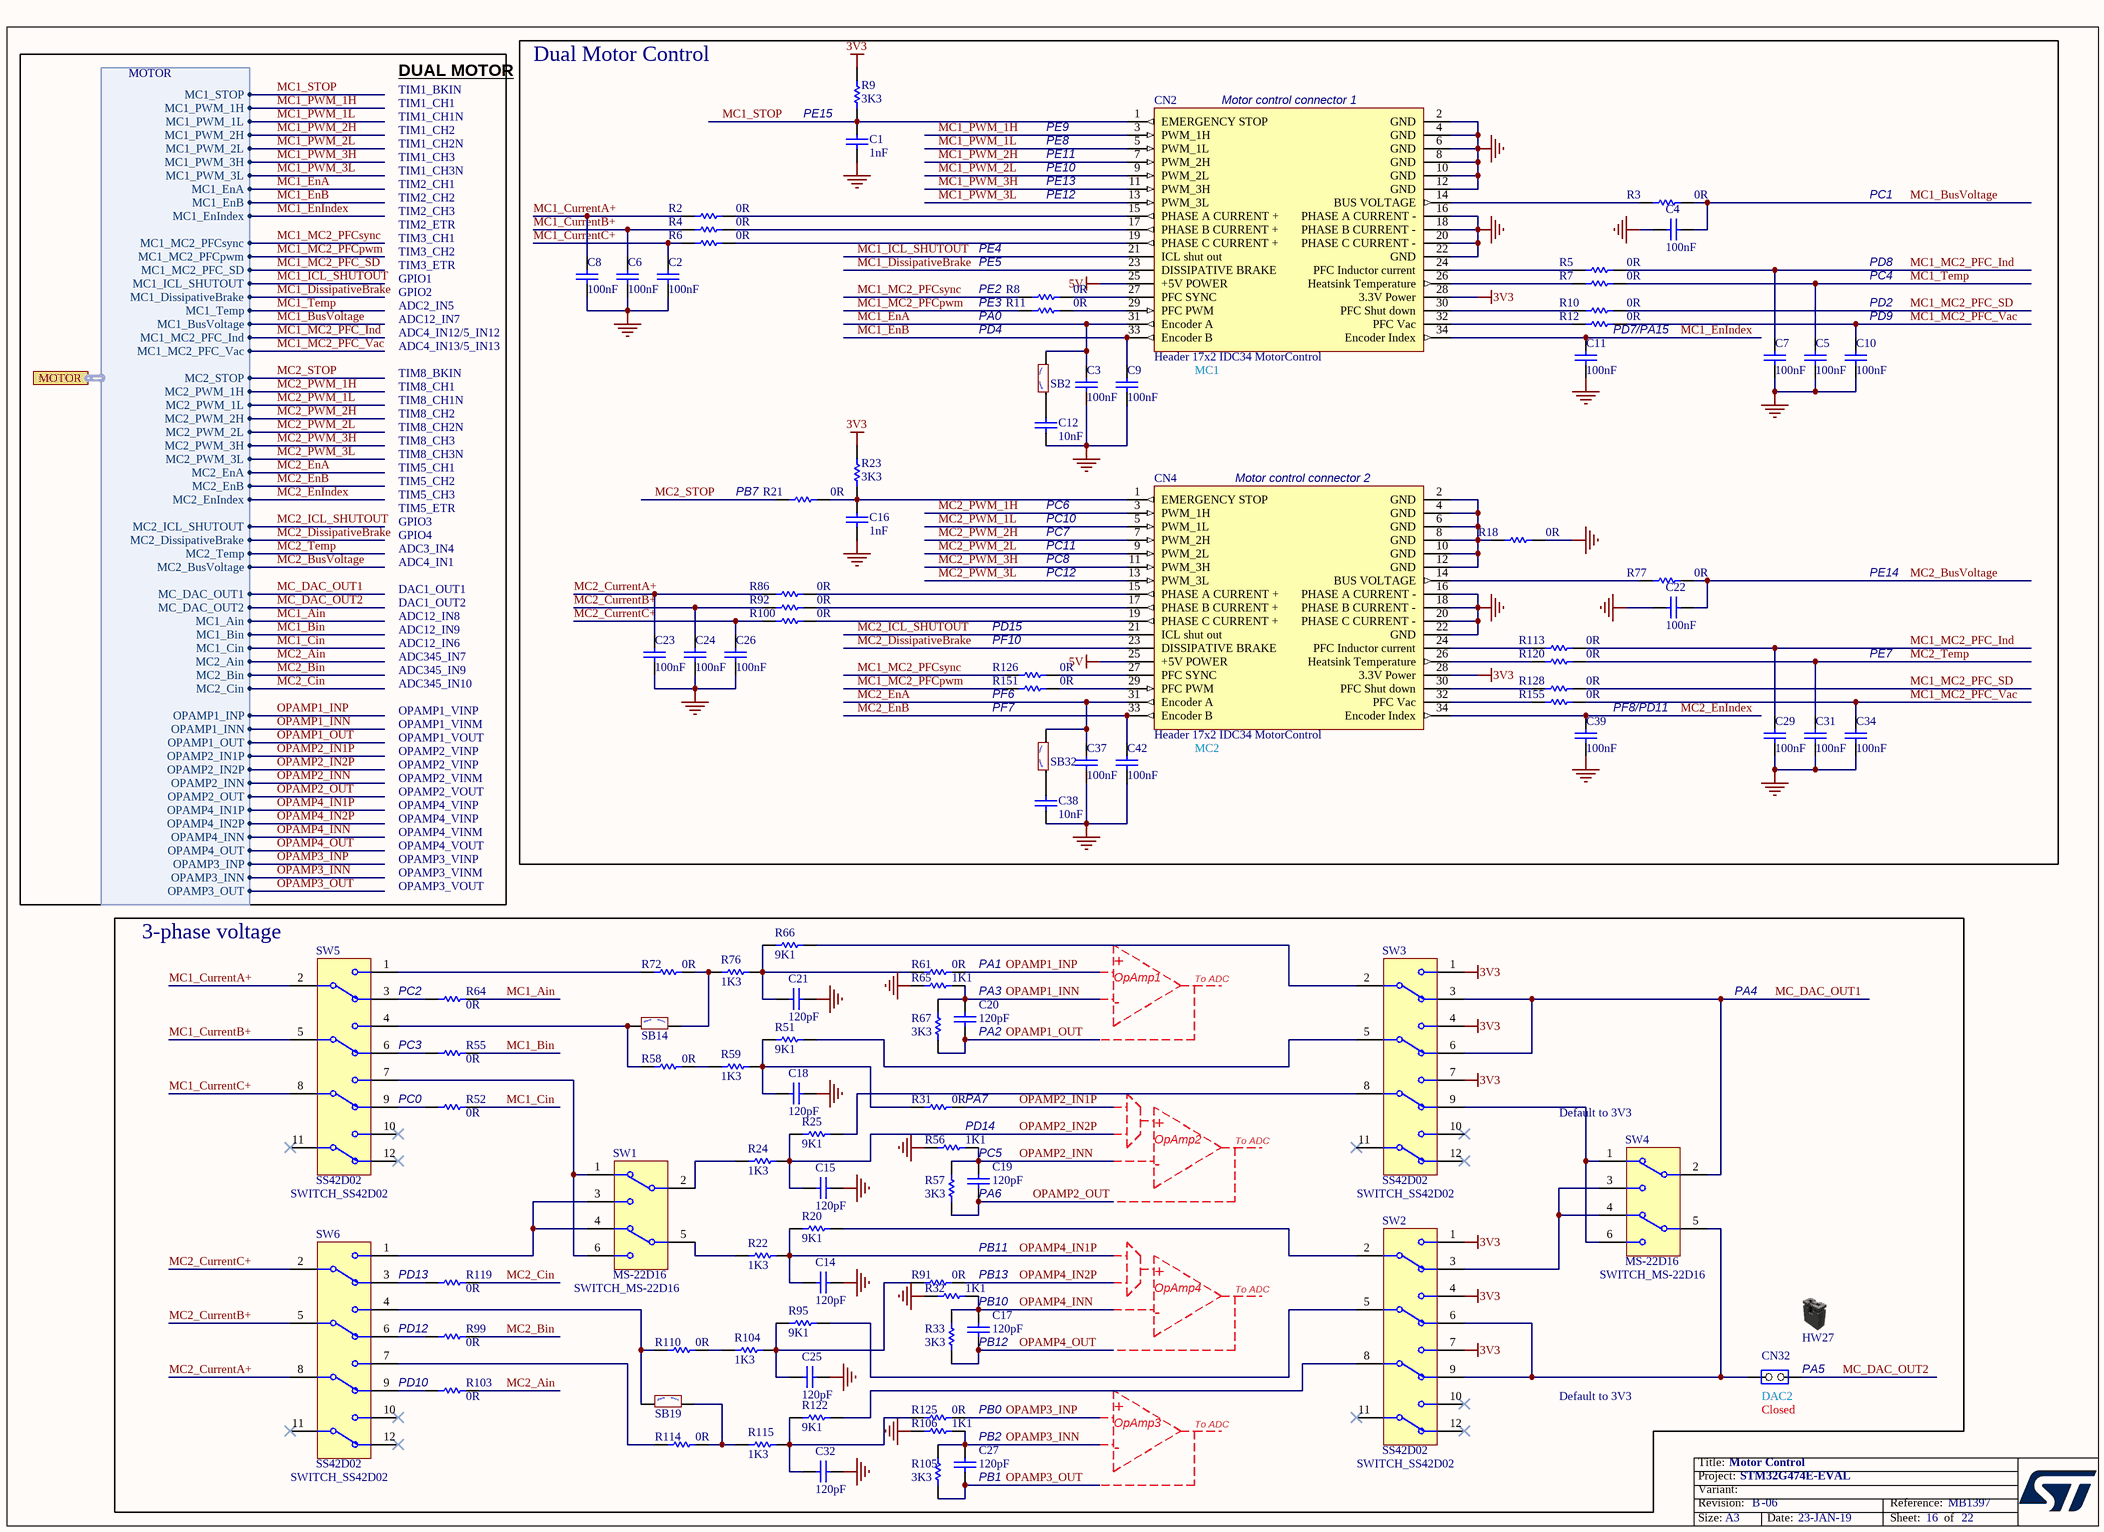
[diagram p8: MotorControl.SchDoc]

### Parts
C1  value 1nF  [C0402]  (hidden comment: Capacitor)
C2  value 100nF  [C0402]  (hidden comment: Capacitor)
C3  value 100nF  [C0402]  (hidden comment: Capacitor)
C4  value 100nF  [C0402]  (hidden comment: Capacitor)
C5  value 100nF  [C0402]  (hidden comment: Capacitor)
C6  value 100nF  [C0402]  (hidden comment: Capacitor)
C7  value 100nF  [C0402]  (hidden comment: Capacitor)
C8  value 100nF  [C0402]  (hidden comment: Capacitor)
C9  value 100nF  [C0402]  (hidden comment: Capacitor)
C10  value 100nF  [C0402]  (hidden comment: Capacitor)
C11  value 100nF  [C0402]  (hidden comment: Capacitor)
C12  value 10nF  [C0402]  (hidden comment: Capacitor)
C14  value 120pF  [C0603]  (hidden comment: Capacitor)
C15  value 120pF  [C0603]  (hidden comment: Capacitor)
C16  value 1nF  [C0402]  (hidden comment: Capacitor)
C17  value 120pF  [C0603]  (hidden comment: Capacitor)
C18  value 120pF  [C0603]  (hidden comment: Capacitor)
C19  value 120pF  [C0603]  (hidden comment: Capacitor)
C20  value 120pF  [C0603]  (hidden comment: Capacitor)
C21  value 120pF  [C0603]  (hidden comment: Capacitor)
C22  value 100nF  [C0402]  (hidden comment: Capacitor)
C23  value 100nF  [C0402]  (hidden comment: Capacitor)
C24  value 100nF  [C0402]  (hidden comment: Capacitor)
C25  value 120pF  [C0603]  (hidden comment: Capacitor)
C26  value 100nF  [C0402]  (hidden comment: Capacitor)
C27  value 120pF  [C0603]  (hidden comment: Capacitor)
C29  value 100nF  [C0402]  (hidden comment: Capacitor)
C31  value 100nF  [C0402]  (hidden comment: Capacitor)
C32  value 120pF  [C0603]  (hidden comment: Capacitor)
C34  value 100nF  [C0402]  (hidden comment: Capacitor)
C37  value 100nF  [C0402]  (hidden comment: Capacitor)
C38  value 10nF  [C0402]  (hidden comment: Capacitor)
C39  value 100nF  [C0402]  (hidden comment: Capacitor)
C42  value 100nF  [C0402]  (hidden comment: Capacitor)
CN2  Header 17x2 IDC34 MotorControl  [CON_SAMTEC_TST-117-01-T-D]
CN4  Header 17x2 IDC34 MotorControl  [CON_SAMTEC_TST-117-01-T-D]
CN32  Jumper_Header 2x1  [CON_SAMTEC_TSW-102-07-G-S]  (value not drawn)
HW27  Shunt Black 2.54mm  (value not drawn)  (mechanical)
R2  value 0R  [R0603]  (hidden comment: Resistor)
R3  value 0R  [R0603]  (hidden comment: Resistor)
R4  value 0R  [R0603]  (hidden comment: Resistor)
R5  value 0R  [R0603]  (hidden comment: Resistor)
R6  value 0R  [R0603]  (hidden comment: Resistor)
R7  value 0R  [R0603]  (hidden comment: Resistor)
R8  value 0R  [R0603]  (hidden comment: Resistor)
R9  value 3K3  [R0402]  (hidden comment: Resistor)
R10  value 0R  [R0603]  (hidden comment: Resistor)
R11  value 0R  [R0603]  (hidden comment: Resistor)
R12  value 0R  [R0603]  (hidden comment: Resistor)
R18  value 0R  [R0603]  (hidden comment: Resistor)
R20  value 9K1  [R0603]  (hidden comment: Resistor)
R21  value 0R  [R0603]  (hidden comment: Resistor)
R22  value 1K3  [R0603]  (hidden comment: Resistor)
R23  value 3K3  [R0402]  (hidden comment: Resistor)
R24  value 1K3  [R0603]  (hidden comment: Resistor)
R25  value 9K1  [R0603]  (hidden comment: Resistor)
R31  value 0R  [R0603]  (hidden comment: Resistor)
R32  value 1K1  [R0603]  (hidden comment: Resistor)
R33  value 3K3  [R0603]  (hidden comment: Resistor)
R51  value 9K1  [R0603]  (hidden comment: Resistor)
R52  value 0R  [R0603]  (hidden comment: Resistor)
R55  value 0R  [R0603]  (hidden comment: Resistor)
R56  value 1K1  [R0603]  (hidden comment: Resistor)
R57  value 3K3  [R0603]  (hidden comment: Resistor)
R58  value 0R  [R0603]  (hidden comment: Resistor)
R59  value 1K3  [R0603]  (hidden comment: Resistor)
R61  value 0R  [R0603]  (hidden comment: Resistor)
R64  value 0R  [R0603]  (hidden comment: Resistor)
R65  value 1K1  [R0603]  (hidden comment: Resistor)
R66  value 9K1  [R0603]  (hidden comment: Resistor)
R67  value 3K3  [R0603]  (hidden comment: Resistor)
R72  value 0R  [R0603]  (hidden comment: Resistor)
R76  value 1K3  [R0603]  (hidden comment: Resistor)
R77  value 0R  [R0603]  (hidden comment: Resistor)
R86  value 0R  [R0603]  (hidden comment: Resistor)
R91  value 0R  [R0603]  (hidden comment: Resistor)
R92  value 0R  [R0603]  (hidden comment: Resistor)
R95  value 9K1  [R0603]  (hidden comment: Resistor)
R99  value 0R  [R0603]  (hidden comment: Resistor)
R100  value 0R  [R0603]  (hidden comment: Resistor)
R103  value 0R  [R0603]  (hidden comment: Resistor)
R104  value 1K3  [R0603]  (hidden comment: Resistor)
R105  value 3K3  [R0603]  (hidden comment: Resistor)
R106  value 1K1  [R0603]  (hidden comment: Resistor)
R110  value 0R  [R0603]  (hidden comment: Resistor)
R113  value 0R  [R0603]  (hidden comment: Resistor)
R114  value 0R  [R0603]  (hidden comment: Resistor)
R115  value 1K3  [R0603]  (hidden comment: Resistor)
R119  value 0R  [R0603]  (hidden comment: Resistor)
R120  value 0R  [R0603]  (hidden comment: Resistor)
R122  value 9K1  [R0603]  (hidden comment: Resistor)
R125  value 0R  [R0603]  (hidden comment: Resistor)
R126  value 0R  [R0603]  (hidden comment: Resistor)
R128  value 0R  [R0603]  (hidden comment: Resistor)
R151  value 0R  [R0603]  (hidden comment: Resistor)
R155  value 0R  [R0603]  (hidden comment: Resistor)
SB2  SB_OFF  [SOLDER-BRIDGE_R0603-0R]  (value not drawn)
SB14  SB_OFF  [SOLDER-BRIDGE_R0603-0R]  (value not drawn)
SB19  SB_OFF  [SOLDER-BRIDGE_R0603-0R]  (value not drawn)
SB32  SB_OFF  [SOLDER-BRIDGE_R0603-0R]  (value not drawn)
SW1  SWITCH_MS-22D16  value MS-22D16  [SWI_DHS-ELECTRONICS_MS-22D16_2P2T]
SW2  SWITCH_SS42D02  value SS42D02  [SWI_DHS-ELECTRONICS_SS42D02_4P2T]
SW3  SWITCH_SS42D02  value SS42D02  [SWI_DHS-ELECTRONICS_SS42D02_4P2T]
SW4  SWITCH_MS-22D16  value MS-22D16  [SWI_DHS-ELECTRONICS_MS-22D16_2P2T]
SW5  SWITCH_SS42D02  value SS42D02  [SWI_DHS-ELECTRONICS_SS42D02_4P2T]
SW6  SWITCH_SS42D02  value SS42D02  [SWI_DHS-ELECTRONICS_SS42D02_4P2T]

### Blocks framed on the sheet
Dual Motor Control: C1-C12 C16 C22-C24 C26 C29 C31 C34 C37-C39 C42 CN2 CN4 R2-R12 R18 R21 R23 R77 R86 R92 R100 R113 R120 R126 R128 R151 R155 SB2 SB32
3-phase voltage: C14 C15 C17-C21 C25 C27 C32 CN32 HW27 R20 R22 R24 R25 R31-R33 R51 R52 R55-R59 R61 R64-R67 R72 R76 R91 R95 R99 R103-R106 R110 R114 R115 R119 R122 R125 SB14 SB19 SW1-SW6

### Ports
MOTOR (harness MOTOR)

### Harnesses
MOTOR: MC1_PWM_1H, MC1_PWM_1L, MC1_PWM_2H, MC1_PWM_2L, MC1_PWM_3H, MC1_PWM_3L, MC1_STOP, MC1_EnA, MC1_EnB, MC1_EnIndex, MC1_MC2_PFCsync, MC1_MC2_PFCpwm, MC1_MC2_PFC_SD, MC1_ICL_SHUTOUT, MC1_DissipativeBrake, MC1_Temp, MC1_BusVoltage, MC1_MC2_PFC_Ind, MC1_MC2_PFC_Vac, MC2_STOP, MC2_PWM_1H, MC2_PWM_1L, MC2_PWM_2H, MC2_PWM_2L, MC2_PWM_3H, MC2_PWM_3L, MC2_EnA, MC2_EnB, MC2_EnIndex, MC2_ICL_SHUTOUT, MC2_DissipativeBrake, MC2_Temp, MC2_BusVoltage, MC_DAC_OUT1, MC_DAC_OUT2, MC1_Ain, MC1_Bin, MC1_Cin, MC2_Ain, MC2_Bin, MC2_Cin, OPAMP1_INP, OPAMP1_INN, OPAMP1_OUT, OPAMP2_IN1P, OPAMP2_IN2P, OPAMP2_INN, OPAMP2_OUT, OPAMP4_IN1P, OPAMP4_IN2P, OPAMP4_INN, OPAMP4_OUT, OPAMP3_INP, OPAMP3_INN, OPAMP3_OUT

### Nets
3V3: CN2.28(3.3V_Power) CN4.28(3.3V_Power) R9.2 R23.2 SW2.1 SW2.4 SW2.7 SW3.1 SW3.4 SW3.7
5V: CN2.25(+5V_POWER) CN4.25(+5V_POWER)
GND: C1.1 C2.1 C3.1 C4.2 C5.1 C6.1 C7.1 C8.1 C9.1 C10.1 C11.1 C12.1 C14.2 C15.2 C16.1 C18.2 C21.2 C22.2 C23.1 C24.1 C25.2 C26.1 C29.1 C31.1 C32.2 C34.1 C37.1 C38.1 C39.1 C42.1 CN2.2(GND) CN2.4(GND) CN2.6(GND) CN2.8(GND) CN2.10(GND) CN2.12(GND) CN2.16(PHASE_A_CURRENT_-) CN2.18(PHASE_B_CURRENT_-) CN2.20(PHASE_C_CURRENT_-) CN2.22(GND) CN4.16(PHASE_A_CURRENT_-) CN4.18(PHASE_B_CURRENT_-) CN4.20(PHASE_C_CURRENT_-) CN4.22(GND) R18.2 R32.1 R56.1 R65.1 R106.1
MC1_Ain: R64.2 ; port MOTOR.MC1_Ain
MC1_Bin: R55.2 ; port MOTOR.MC1_Bin
MC1_BusVoltage: C4.1 R3.2 ; port MOTOR.MC1_BusVoltage
MC1_Cin: R52.2 ; port MOTOR.MC1_Cin
MC1_CurrentA+: C8.2 R2.1 SW5.2
MC1_CurrentB+: C6.2 R4.1 SW5.5
MC1_CurrentC+: C2.2 R6.1 SW5.8
MC1_DissipativeBrake: CN2.23(DISSIPATIVE_BRAKE) ; port MOTOR.MC1_DissipativeBrake
MC1_EnA: C3.2 CN2.31(Encoder_A) SB2.1 ; port MOTOR.MC1_EnA
MC1_EnB: C9.2 CN2.33(Encoder_B) ; port MOTOR.MC1_EnB
MC1_EnIndex: C11.2 CN2.34(Encoder_Index) ; port MOTOR.MC1_EnIndex
MC1_ICL_SHUTOUT: CN2.21(ICL_shut_out) ; port MOTOR.MC1_ICL_SHUTOUT
MC1_MC2_PFC_Ind: C7.2 C29.2 R5.2 R113.2 ; port MOTOR.MC1_MC2_PFC_Ind
MC1_MC2_PFC_SD: R10.2 R128.2 ; port MOTOR.MC1_MC2_PFC_SD
MC1_MC2_PFC_Vac: C10.2 C34.2 R12.2 R155.2 ; port MOTOR.MC1_MC2_PFC_Vac
MC1_MC2_PFCpwm: R11.1 R151.1 ; port MOTOR.MC1_MC2_PFCpwm
MC1_MC2_PFCsync: R8.1 R126.1 ; port MOTOR.MC1_MC2_PFCsync
MC1_PWM_1H: CN2.3(PWM_1H) ; port MOTOR.MC1_PWM_1H
MC1_PWM_1L: CN2.5(PWM_1L) ; port MOTOR.MC1_PWM_1L
MC1_PWM_2H: CN2.7(PWM_2H) ; port MOTOR.MC1_PWM_2H
MC1_PWM_2L: CN2.9(PWM_2L) ; port MOTOR.MC1_PWM_2L
MC1_PWM_3H: CN2.11(PWM_3H) ; port MOTOR.MC1_PWM_3H
MC1_PWM_3L: CN2.13(PWM_3L) ; port MOTOR.MC1_PWM_3L
MC1_STOP: C1.2 CN2.1(EMERGENCY_STOP) R9.1 ; port MOTOR.MC1_STOP
MC1_Temp: C5.2 R7.2 ; port MOTOR.MC1_Temp
MC2_Ain: R103.2 ; port MOTOR.MC2_Ain
MC2_Bin: R99.2 ; port MOTOR.MC2_Bin
MC2_BusVoltage: C22.1 R77.2 ; port MOTOR.MC2_BusVoltage
MC2_Cin: R119.2 ; port MOTOR.MC2_Cin
MC2_CurrentA+: C23.2 R86.1 SW6.8
MC2_CurrentB+: C24.2 R92.1 SW6.5
MC2_CurrentC+: C26.2 R100.1 SW6.2
MC2_DissipativeBrake: CN4.23(DISSIPATIVE_BRAKE) ; port MOTOR.MC2_DissipativeBrake
MC2_EnA: C37.2 CN4.31(Encoder_A) SB32.1 ; port MOTOR.MC2_EnA
MC2_EnB: C42.2 CN4.33(Encoder_B) ; port MOTOR.MC2_EnB
MC2_EnIndex: C39.2 CN4.34(Encoder_Index) ; port MOTOR.MC2_EnIndex
MC2_ICL_SHUTOUT: CN4.21(ICL_shut_out) ; port MOTOR.MC2_ICL_SHUTOUT
MC2_PWM_1H: CN4.3(PWM_1H) ; port MOTOR.MC2_PWM_1H
MC2_PWM_1L: CN4.5(PWM_1L) ; port MOTOR.MC2_PWM_1L
MC2_PWM_2H: CN4.7(PWM_2H) ; port MOTOR.MC2_PWM_2H
MC2_PWM_2L: CN4.9(PWM_2L) ; port MOTOR.MC2_PWM_2L
MC2_PWM_3H: CN4.11(PWM_3H) ; port MOTOR.MC2_PWM_3H
MC2_PWM_3L: CN4.13(PWM_3L) ; port MOTOR.MC2_PWM_3L
MC2_STOP: R21.1 ; port MOTOR.MC2_STOP
MC2_Temp: C31.2 R120.2 ; port MOTOR.MC2_Temp
MC_DAC_OUT1: SW3.3 SW3.6 SW4.2 ; port MOTOR.MC_DAC_OUT1
MC_DAC_OUT2: CN32.1(COMMON) ; port MOTOR.MC_DAC_OUT2
OPAMP1_INN: C20.1 R65.2 R67.2 ; port MOTOR.OPAMP1_INN
OPAMP1_INP: R61.2 ; port MOTOR.OPAMP1_INP
OPAMP1_OUT: C20.2 R67.1 ; port MOTOR.OPAMP1_OUT
OPAMP2_IN1P: R31.2 ; port MOTOR.OPAMP2_IN1P
OPAMP2_IN2P: C15.1 R24.2 R25.1 ; port MOTOR.OPAMP2_IN2P
OPAMP2_INN: C19.1 R56.2 R57.2 ; port MOTOR.OPAMP2_INN
OPAMP2_OUT: C19.2 R57.1 ; port MOTOR.OPAMP2_OUT
OPAMP3_INN: C27.1 R105.2 R106.2 ; port MOTOR.OPAMP3_INN
OPAMP3_INP: R125.2 ; port MOTOR.OPAMP3_INP
OPAMP3_OUT: C27.2 R105.1 ; port MOTOR.OPAMP3_OUT
OPAMP4_IN1P: C14.1 R20.1 R22.2 ; port MOTOR.OPAMP4_IN1P
OPAMP4_IN2P: R91.2 ; port MOTOR.OPAMP4_IN2P
OPAMP4_INN: C17.1 R32.2 R33.2 ; port MOTOR.OPAMP4_INN
OPAMP4_OUT: C17.2 R33.1 ; port MOTOR.OPAMP4_OUT
NetC12_2: C12.2 SB2.2
NetC16_2: C16.2 CN4.1(EMERGENCY_STOP) R21.2 R23.1
NetC18_1: C18.1 R31.1 R51.1 R59.2
NetC21_1: C21.1 R61.1 R66.1 R76.2
NetC25_1: C25.1 R91.1 R95.1 R104.2
NetC32_1: C32.1 R115.2 R122.1 R125.1
NetC38_2: C38.2 SB32.2
NetCN2_14: CN2.14(BUS_VOLTAGE) R3.1
NetCN2_15: CN2.15(PHASE_A_CURRENT_+) R2.2
NetCN2_17: CN2.17(PHASE_B_CURRENT_+) R4.2
NetCN2_19: CN2.19(PHASE_C_CURRENT_+) R6.2
NetCN2_24: CN2.24(PFC_Inductor_current) R5.1
NetCN2_26: CN2.26(Heatsink_Temperature) R7.1
NetCN2_27: CN2.27(PFC_SYNC) R8.2
NetCN2_29: CN2.29(PFC_PWM) R11.2
NetCN2_30: CN2.30(PFC_Shut_down) R10.1
NetCN2_32: CN2.32(PFC_Vac) R12.1
NetCN4_2: CN4.2(GND) CN4.4(GND) CN4.6(GND) CN4.8(GND) CN4.10(GND) CN4.12(GND) R18.1
NetCN4_14: CN4.14(BUS_VOLTAGE) R77.1
NetCN4_15: CN4.15(PHASE_A_CURRENT_+) R86.2
NetCN4_17: CN4.17(PHASE_B_CURRENT_+) R92.2
NetCN4_19: CN4.19(PHASE_C_CURRENT_+) R100.2
NetCN4_24: CN4.24(PFC_Inductor_current) R113.1
NetCN4_26: CN4.26(Heatsink_Temperature) R120.1
NetCN4_27: CN4.27(PFC_SYNC) R126.2
NetCN4_29: CN4.29(PFC_PWM) R151.2
NetCN4_30: CN4.30(PFC_Shut_down) R128.1
NetCN4_32: CN4.32(PFC_Vac) R155.1
NetCN32_2: CN32.2(NO) SW2.6 SW2.9 SW4.5
NetR20_2: R20.2 SW2.2
NetR22_1: R22.1 SW1.5
NetR24_1: R24.1 SW1.2
NetR25_2: R25.2 SW3.8
NetR51_2: R51.2 SW3.5
NetR52_1: R52.1 SW5.9
NetR55_1: R55.1 SW5.6
NetR58_1: R58.1 SB14.1 SW5.4
NetR58_2: R58.2 R59.1
NetR64_1: R64.1 SW5.3
NetR66_2: R66.2 SW3.2
NetR72_1: R72.1 SW5.1
NetR72_2: R72.2 R76.1 SB14.2
NetR95_2: R95.2 SW2.5
NetR99_1: R99.1 SW6.6
NetR103_1: R103.1 SW6.9
NetR104_1: R104.1 R110.2
NetR110_1: R110.1 SB19.1 SW6.4
NetR114_1: R114.1 SW6.7
NetR114_2: R114.2 R115.1 SB19.2
NetR119_1: R119.1 SW6.3
NetR122_2: R122.2 SW2.8
NetSW1_1: SW1.1 SW1.6 SW5.7
NetSW1_3: SW1.3 SW1.4 SW6.1
NetSW2_3: SW2.3 SW4.3 SW4.4
NetSW3_9: SW3.9 SW4.1 SW4.6

Not connected (* = marked no-connect by the designer): SW2 10* 11* 12*; SW3 10* 11* 12*; SW5 10* 11* 12*; SW6 10* 11* 12*

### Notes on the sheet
- DUAL MOTOR
- PE15
- PE9
- (near CN2) Motor control connector 1
- PE8
- PE11
- PE10
- PE13
- PE12
- PC1
- PE5
- PE4
- PD8
- PA0
- PD4
- PE2
- PE3
- (near R12) PD7/PA15
- PC4
- PD2
- (near C10) PD9
- (near CN2) MC1
- (near R21) PB7
- PC6
- PC10
- PC7
- (near CN4) Motor control connector 2
- PC11
- PC8
- PC12
- PE14
- PF10
- PD15
- PE7
- PF6
- (near R151) PF7
- PF8/PD11
- (near CN4) MC2
- TIM1_BKIN
  TIM1_CH1
  TIM1_CH1N
  TIM1_CH2
  TIM1_CH2N
  TIM1_CH3
  TIM1_CH3N
  TIM2_CH1
  TIM2_CH2
  TIM2_CH3
  TIM2_ETR
  TIM3_CH1
  TIM3_CH2
  TIM3_ETR
  GPIO1
  GPIO2
  ADC2_IN5
  ADC12_IN7
  ADC4_IN12/5_IN12
  ADC4_IN13/5_IN13
  TIM8_BKIN
  TIM8_CH1
  TIM8_CH1N
  TIM8_CH2
  TIM8_CH2N
  TIM8_CH3
  TIM8_CH3N
  TIM5_CH1
  TIM5_CH2
  TIM5_CH3
  TIM5_ETR
  GPIO3
  GPIO4
  ADC3_IN4
  ADC4_IN1
  DAC1_OUT1
  DAC1_OUT2
  ADC12_IN8
  ADC12_IN9
  ADC12_IN6
  ADC345_IN7
  ADC345_IN9
  ADC345_IN10
  OPAMP1_VINP
  OPAMP1_VINM
  OPAMP1_VOUT
  OPAMP2_VINP
  OPAMP2_VINP
  OPAMP2_VINM
  OPAMP2_VOUT
  OPAMP4_VINP
  OPAMP4_VINP
  OPAMP4_VINM
  OPAMP4_VOUT
  OPAMP3_VINP
  OPAMP3_VINM
  OPAMP3_VOUT
- PC2
- PA1
- PA3
- +
- -
- OpAmp1
- To ADC
- PA4
- PC3
- (near C20) PA2
- PC0
- (near R31) PA7
- PD14
- OpAmp2
- (near SW3) Default to 3V3
- PC5
- (near C19) PA6
- PD13
- PB11
- PB13
- PD12
- PB10
- (near C17) PB12
- OpAmp4
- PD10
- PB0
- (near SW2) Default to 3V3
- (near CN32) DAC2
- (near CN32) Closed
- (near CN32) PA5
- PB2
- (near C27) PB1
- OpAmp3

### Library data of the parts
C1 C16 = MCD-00198: Capacitor, MLCC, 1nF, 16V, X7R, 10%, 0402, T=0.5mm; Manufacturer_Part_Number: CC0402KRX7R7BB102; Manufacturer: YAGEO; Provided_By: SUBCO; Initial_Board_Reference: MBxxxx; Path: ws/MCD_ApplicationBoards/Lists/MCDPARTSdatabase; Item Type: Item
C2-C11 C22-C24 C26 C29 C31 C34 C37 C39 C42 = MCD-00006: as C93 on sheet Audio
C12 C38 = MCD-00011: Capacitor, MLCC, 10nF, 16V, X7R, 10%, 0402, T=0.5mm; Manufacturer_Part_Number: CC0402KRX7R7BB103; Manufacturer: YAGEO; Provided_By: SUBCO; Initial_Board_Reference: MB1274; Path: ws/MCD_ApplicationBoards/Lists/MCDPARTSdatabase; Item Type: Item
C14 C15 C17-C21 C25 C27 C32 = MCD-01188: Capacitor,120pF,50V,NPO,5%,0603; Manufacturer_Part_Number: CC0603JRNPO9BN121; Manufacturer: YAGEO; Provided_By: SUBCO; Initial_Board_Reference: MB1397; Remark: MPN is confirm, even if datasheet not mention it.Eric: updated new MPN with new datasheet.; Path: ws/MCD_ApplicationBoards/Lists/MCDPARTSdatabase; Item Type: Item
CN2 CN4 = MCD-00583: Header, 17x2, 2.54mm, VR, TH, Height 8.89mm/2.92mm, shrouded; Manufacturer_Part_Number: TST-117-01-T-D; Manufacturer: SAMTEC; Part_Type: Connector; Alternate_Manufacturer_Part_Number: BHFS03-34G01BT1; Alternate_Manufacturer: WINPIN; Provided_By: SUBCO; Initial_Board_Reference: MB1331; Path: ws/MCD_ApplicationBoards/Lists/MCDPARTSdatabase; Item Type: Item
CN32 = MCD-00045: as JP2 on sheet FDCAN
HW27 = MCD-00043: SHUNT 2.54mm BLACK; Part_Type: Mechanical; Manufacturer_Part_Number: SNT-100-BK-G; Manufacturer: SAMTEC; Provided_By: SUBCO; Initial_Board_Reference: MB1274; Value: SNT-100-BK-G; Path: ws/MCD_ApplicationBoards/Lists/MCDPARTSdatabase; Item Type: Item
R2-R8 R10-R12 R18 R21 R31 R52 R55 R58 R61 R64 R72 R77 R86 R91 R92 R99 R100 R103 R110 R113 R114 R119 R120 R125 R126 R128 R151 R155 = MCD-00056: as R257 on sheet Audio
R9 R23 = MCD-00184: Resistor,3K3,0402,1%,1/16W; Manufacturer_Part_Number: RC0402FR-073K3L; Manufacturer: YAGEO; Provided_By: SUBCO; Initial_Board_Reference: MBxxxx; Path: ws/MCD_ApplicationBoards/Lists/MCDPARTSdatabase; Item Type: Item
R20 R25 R51 R66 R95 R122 = MCD-00540: Resistor,9K1,0603,1%,1/10W; Manufacturer_Part_Number: RC0603FR-079K1L; Manufacturer: YAGEO; Provided_By: SUBCO; Initial_Board_Reference: MBxxxx; Path: ws/MCD_ApplicationBoards/Lists/MCDPARTSdatabase; Item Type: Item
R22 R24 R59 R76 R104 R115 = MCD-00382: Resistor,1K3,0603,1%,1/10W; Manufacturer_Part_Number: RC0603FR-071K3L; Manufacturer: YAGEO; Provided_By: SUBCO; Initial_Board_Reference: MBxxxx; Path: ws/MCD_ApplicationBoards/Lists/MCDPARTSdatabase; Item Type: Item
R32 R56 R65 R106 = MCD-00364: Resistor,1K1,0603,1%,1/10W; Manufacturer_Part_Number: RC0603FR-071K1L; Manufacturer: YAGEO; Provided_By: SUBCO; Initial_Board_Reference: MBxxxx; Path: ws/MCD_ApplicationBoards/Lists/MCDPARTSdatabase; Item Type: Item
R33 R57 R67 R105 = MCD-00352: Resistor,3K3,0603,1%,1/10W; Manufacturer_Part_Number: RC0603FR-073K3L; Manufacturer: YAGEO; Provided_By: SUBCO; Initial_Board_Reference: MBxxxx; Path: ws/MCD_ApplicationBoards/Lists/MCDPARTSdatabase; Item Type: Item
SB2 SB14 SB19 SB32 = MCD-00072: as SB36 on sheet QSPI_Memory
SW1 SW4 = MCD-01180: vertical slider switch 2x(A to 2B); Part_Type: Connector; Manufacturer: Dongguan Huan Sheng Electronics Co.,Ltd.; Provided_By: SUBCO; Initial_Board_Reference: MB1397; Path: ws/MCD_ApplicationBoards/Lists/MCDPARTSdatabase; Item Type: Item
SW2 SW3 SW5 SW6 = MCD-01179: Vertical slide switch 4x (A to 2B); Part_Type: Connector; Manufacturer: Dongguan Huan Sheng Electronics Co.,Ltd.; Provided_By: SUBCO; Initial_Board_Reference: MB1397; Path: ws/MCD_ApplicationBoards/Lists/MCDPARTSdatabase; Item Type: Item

## Sheet SmartCard.SchDoc: Smart Card
size A4; Date: Not used; ApprovedBy: Not used; CheckedBy: Not used; Author: Not used; CompanyName: STMicroelectronics; DrawnBy: Not used; Engineer: Not used; Organization: Not used; Address1: Not used; Address2: Not used; Address3: Not used; Address4: Not used; DocumentNumber: Not used; Revision: Not used; SheetNumber: 15; SheetTotal: 22
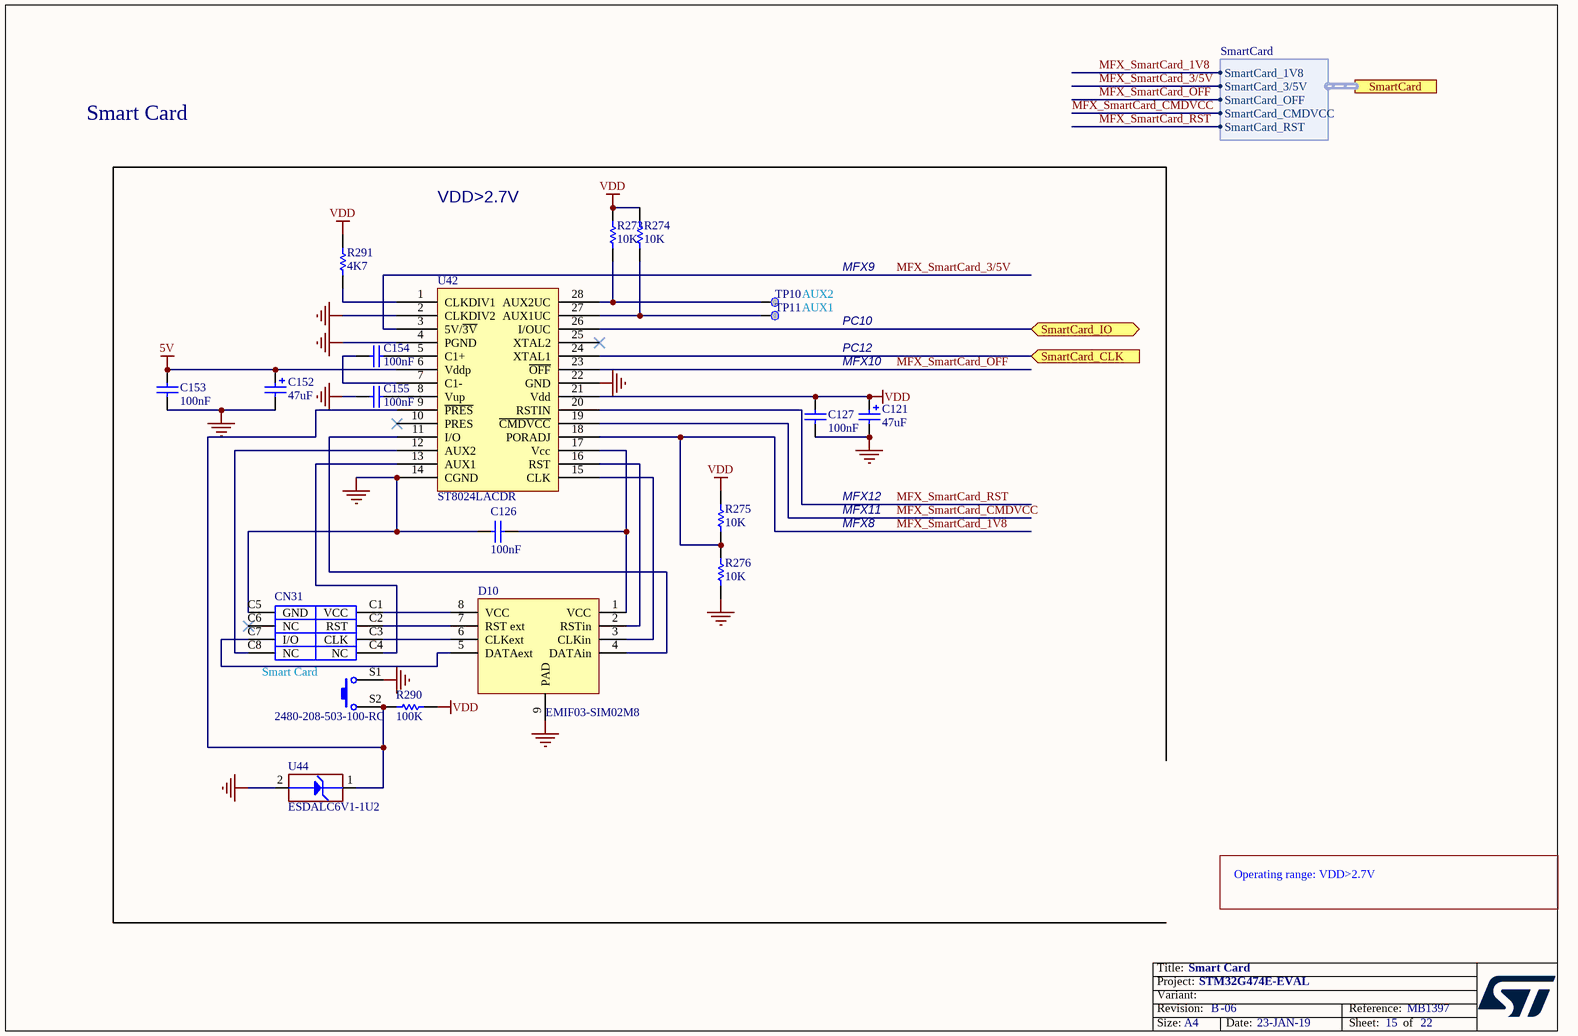
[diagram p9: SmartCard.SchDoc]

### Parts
C121  value 47uF  [CPOL_TAJ-C_2312_H2P6]  (hidden comment: Cap_POL_TANA)
C126  value 100nF  [C0603]  (hidden comment: Capacitor)
C127  value 100nF  [C0603]  (hidden comment: Capacitor)
C152  value 47uF  [CPOL_TAJ-C_2312_H2P6]  (hidden comment: Cap_POL_TANA)
C153  value 100nF  [C0603]  (hidden comment: Capacitor)
C154  value 100nF  [C0603]  (hidden comment: Capacitor)
C155  value 100nF  [C0603]  (hidden comment: Capacitor)
CN31  value 2480-208-503-100-RC  [CON_CARD-SOCKET_GUANG-LIAN-WEI_2480-208-503-100-RC]  (hidden comment: Please to check it carefuly. Pin 8 and 9 not clearly define on datasheet. Need to validate with schematics symbol)
D10  EMIF03-SIM02M8  [ESD_UQFN8-EPAD_1P7X1P5_P040]
R273  value 10K  [R0603]  (hidden comment: Resistor)
R274  value 10K  [R0603]  (hidden comment: Resistor)
R275  value 10K  [R0603]  (hidden comment: Resistor)
R276  value 10K  [R0603]  (hidden comment: Resistor)
R290  value 100K  [R0603]  (hidden comment: Resistor)
R291  value 4K7  [R0402]  (hidden comment: Resistor)
TP10  Test Point  [TP_SMD_1MM]  (value not drawn)  (no BOM)
TP11  Test Point  [TP_SMD_1MM]  (value not drawn)  (no BOM)
U42  value ST8024LACDR  [ICC_SO28_18P10X7P60_P127]  (hidden comment: ST8024CTR)
U44  value ESDALC6V1-1U2  [ESD_ST0201]  (hidden comment: ESD-TRANSIL)

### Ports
SmartCard (harness SmartCard), SmartCard_CLK (in), SmartCard_IO (bidir)

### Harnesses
SmartCard: SmartCard_1V8, SmartCard_3/5V, SmartCard_OFF, SmartCard_CMDVCC, SmartCard_RST

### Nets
5V: C152.1 C153.2 U42.6(Vddp)
GND: C121.2 C126.2 C127.1 C152.2 C153.1 C155.2 CN31.C5(GND) CN31.S1 D10.9(PAD) R276.1 U42.2(CLKDIV2) U42.4(PGND) U42.14(CGND) U42.22(GND) U44.2(GND)
VDD: C121.1 C127.2 R273.2 R274.2 R275.2 R290.2 R291.2 U42.21(Vdd)
MFX_SmartCard_1V8: R275.1 R276.2 U42.18(PORADJ) ; port SmartCard.SmartCard_1V8
MFX_SmartCard_3/5V: U42.3(5V/~{3V}) ; port SmartCard.SmartCard_3/5V
MFX_SmartCard_CMDVCC: U42.19(~{CMDVCC}) ; port SmartCard.SmartCard_CMDVCC
MFX_SmartCard_OFF: U42.23(~{OFF}) ; port SmartCard.SmartCard_OFF
MFX_SmartCard_RST: U42.20(RSTIN) ; port SmartCard.SmartCard_RST
SmartCard_CLK: U42.24(XTAL1) ; port SmartCard_CLK
SmartCard_IO: U42.26(I/OUC) ; port SmartCard_IO
NetC126_1: C126.1 D10.1(VCC) U42.17(Vcc)
NetC154_1: C154.1 U42.5(C1+)
NetC154_2: C154.2 U42.7(C1-)
NetC155_1: C155.1 U42.8(Vup)
NetCN31_C1: CN31.C1(VCC) D10.8(VCC)
NetCN31_C2: CN31.C2(RST) D10.7(RST_ext)
NetCN31_C3: CN31.C3(CLK) D10.6(CLKext)
NetCN31_C4: CN31.C4(NC) U42.13(AUX1)
NetCN31_C7: CN31.C7(I/O) D10.5(DATAext)
NetCN31_C8: CN31.C8(NC) U42.12(AUX2)
NetCN31_S2: CN31.S2 R290.1 U42.9(~{PRES}) U44.1(IO1)
NetD10_2: D10.2(RSTin) U42.16(RST)
NetD10_3: D10.3(CLKin) U42.15(CLK)
NetD10_4: D10.4(DATAin) U42.11(I/O)
NetR273_1: R273.1 TP10.1 U42.28(AUX2UC)
NetR274_1: R274.1 TP11.1 U42.27(AUX1UC)
NetR291_1: R291.1 U42.1(CLKDIV1)

Not connected (* = marked no-connect by the designer): CN31 C6(NC)*; U42 10(PRES)* 25(XTAL2)*

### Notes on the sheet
- Smart Card
- VDD>2.7V
- AUX2
- AUX1
- MFX9
- MFX10
- PC12
- PC10
- MFX12
- MFX11
- MFX8
- (near CN31) Smart Card
- Operating range: VDD>2.7V

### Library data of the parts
C121 C152 = MCD-00559: Capacitor, Tantalum, 47uF, 16V, 10%, TypeC; Manufacturer_Part_Number: TAJC476K016RNJ; Manufacturer: AVX; Provided_By: SUBCO; Initial_Board_Reference: MB1331; Path: ws/MCD_ApplicationBoards/Lists/MCDPARTSdatabase; Item Type: Item
C126 C127 C153-C155 = MCD-00211: as C64 on sheet LCD&SDcard
CN31 = Smart_card_2480-208-503-100-RC: IC Card Socket 8 pin, SMT Open for Smartcard; Internal_Part_Number: MCD-01175; Part_Type: Connector; Manufacturer: GUANG LIAN WEI; Provided_By: Subcon; Initial_Board_Reference: MB1397
D10 = MCD-01229: 3 line IPAD, EMI filter for SIM card applications; Part_Type: Diode; Manufacturer: STMICROELECTRONICS; BMS_Part_Number: 9179047; Provided_By: SUBCO with ST control; Initial_Board_Reference: MB1397; Path: ws/MCD_ApplicationBoards/Lists/MCDPARTSdatabase; Item Type: Item
R273-R276 = MCD-00220: as R219 on sheet LCD&SDcard
R290 = MCD-00223: as R218 on sheet LCD&SDcard
R291 = MCD-00065: as R237 on sheet Audio
TP10 TP11 = MCD-00074: Test Point 1mm; Part_Type: Mechanical; Initial_Board_Reference: MB1274; Path: ws/MCD_ApplicationBoards/Lists/MCDPARTSdatabase; Item Type: Item
U42 = MCD-01162: Smartcard interfaces; Part_Type: IC; Manufacturer: STMICROELECTRONICS; BMS_Part_Number: 9177831; Provided_By: SUBCO with ST control; Initial_Board_Reference: MB1397; Remark: idem ST8024CTR; Path: ws/MCD_ApplicationBoards/Lists/MCDPARTSdatabase; Item Type: Item
U44 = MCD-00170: as U52 on sheet LCD&SDcard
